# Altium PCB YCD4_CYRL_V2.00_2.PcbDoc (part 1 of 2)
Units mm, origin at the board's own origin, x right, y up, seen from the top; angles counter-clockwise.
Board outline 53 x 53 mm, 6 copper layers (Top Layer, Mid-Layer 1, Mid-Layer 3, Mid-Layer 4, Mid-Layer 5, Bottom Layer), stack 0.996 mm thick; 207 components, 114 nets, 645 pads, 437 vias.
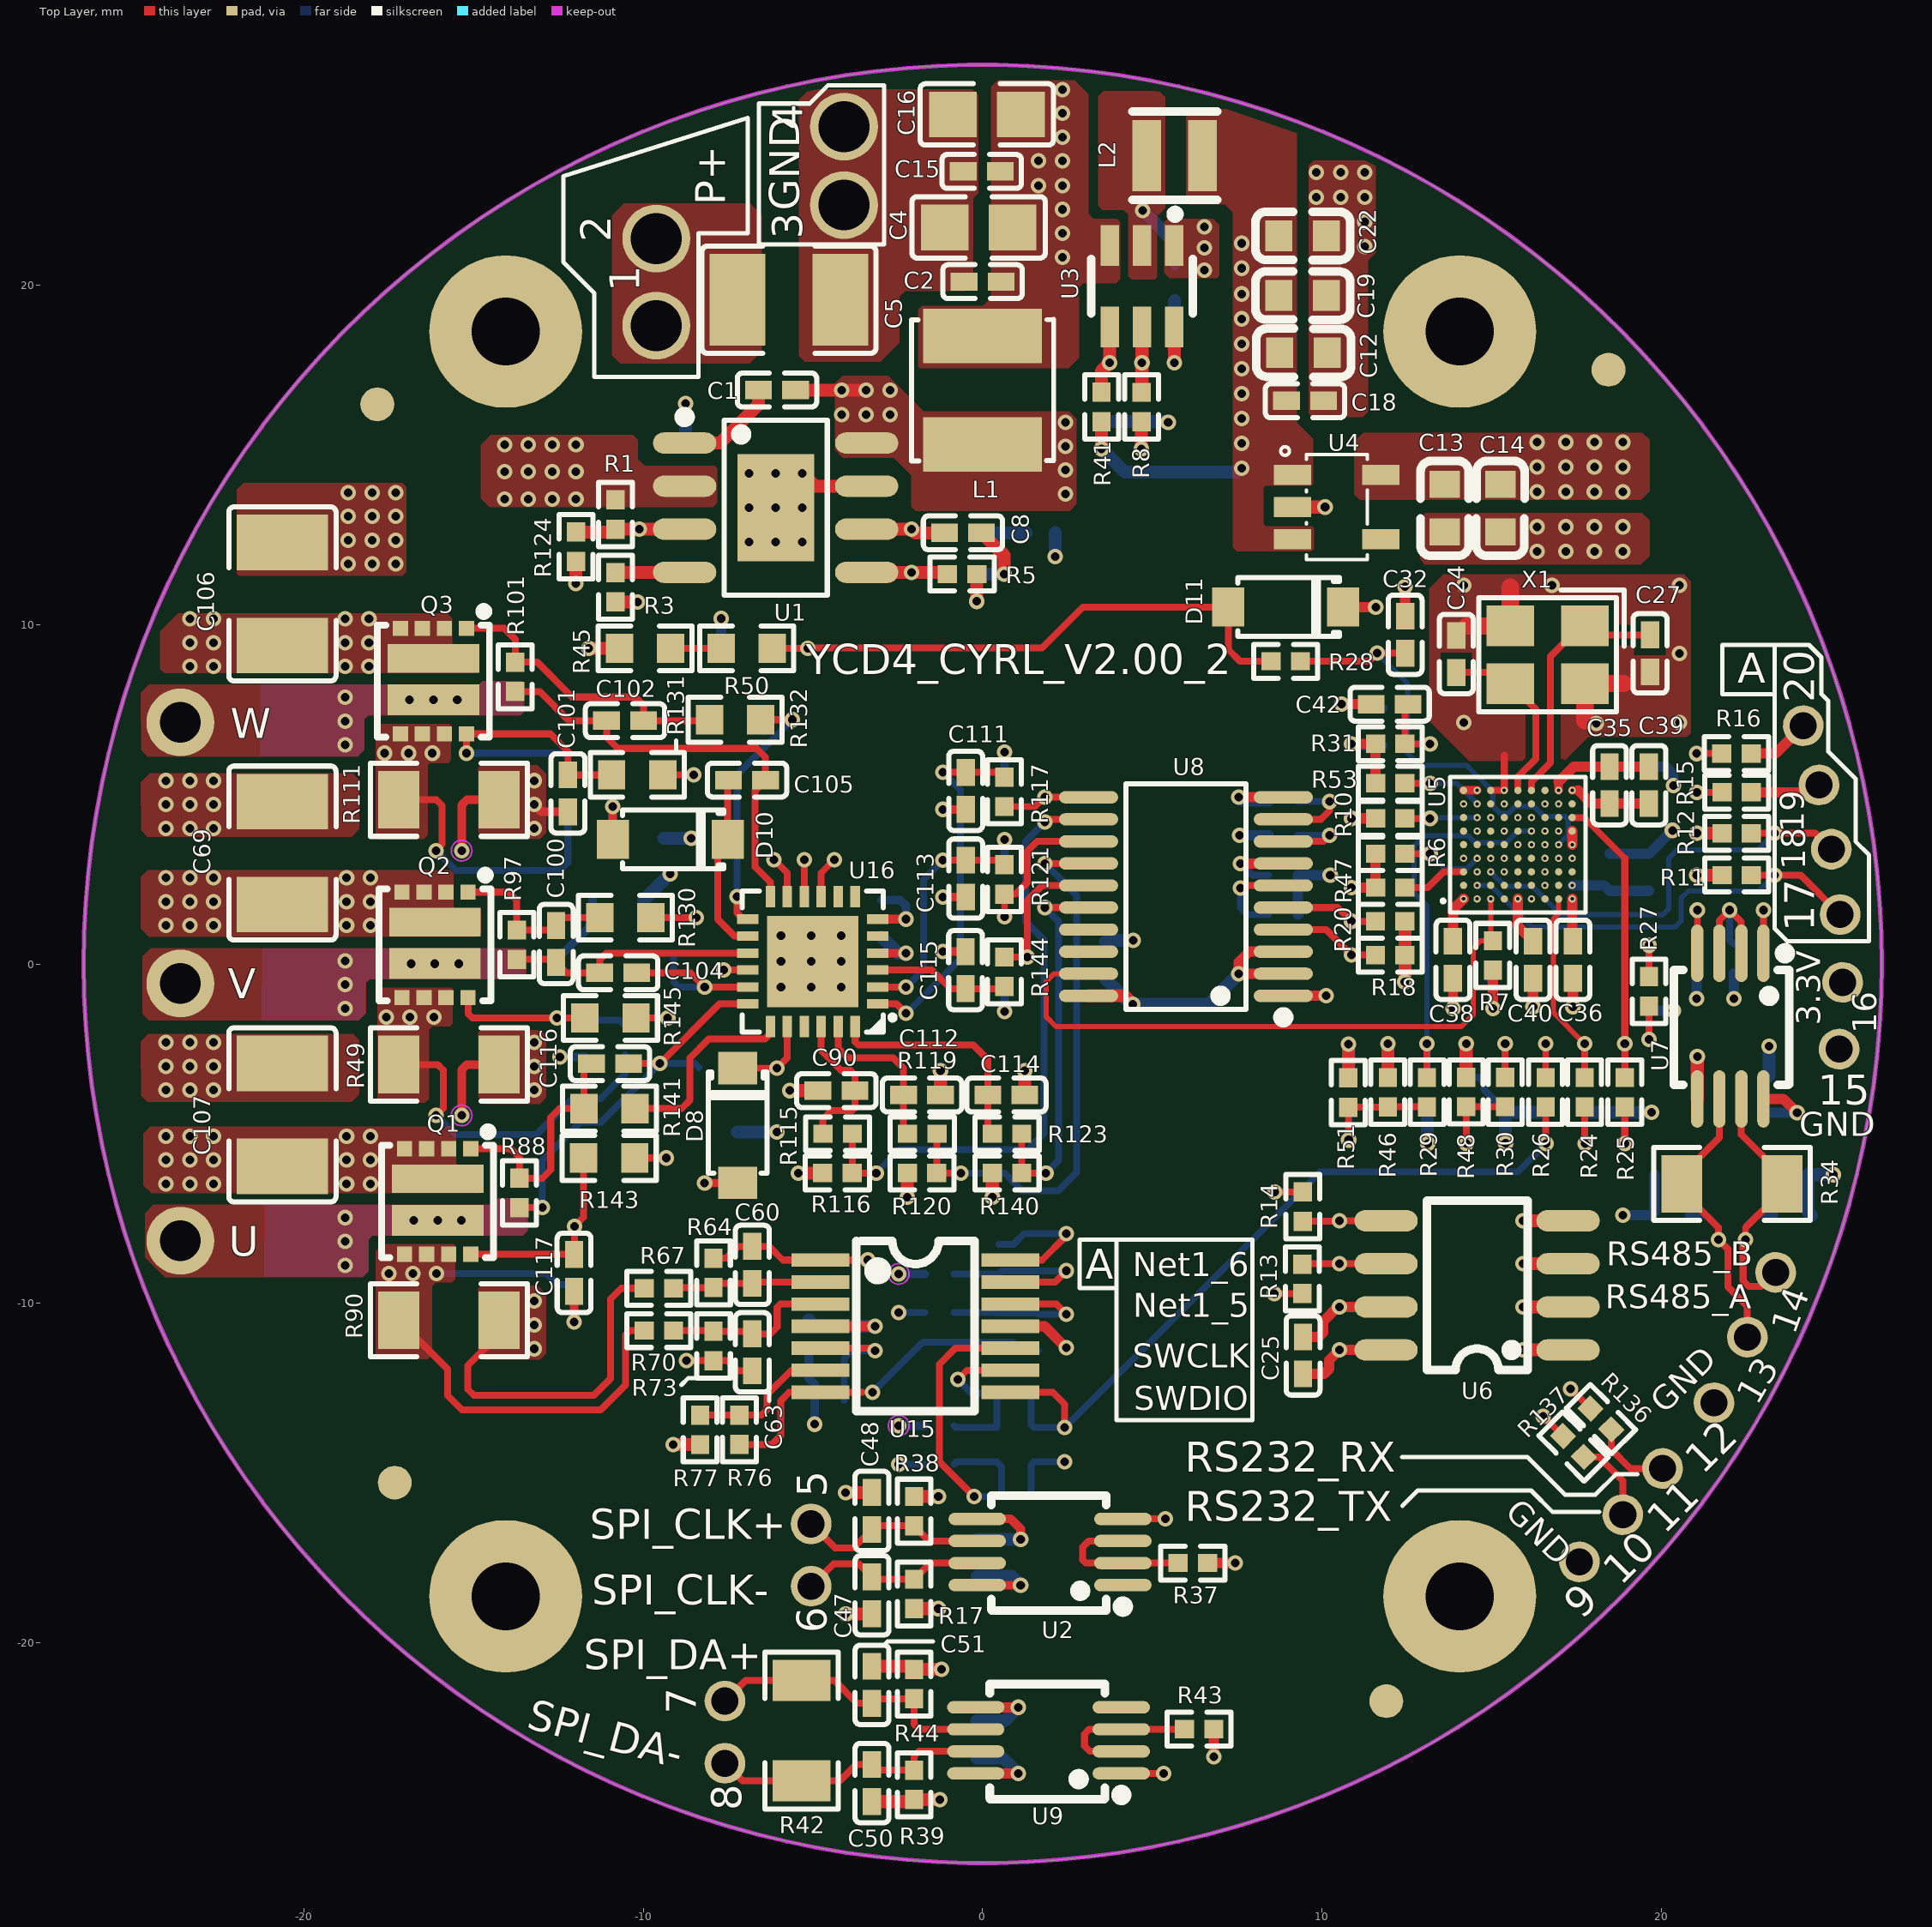
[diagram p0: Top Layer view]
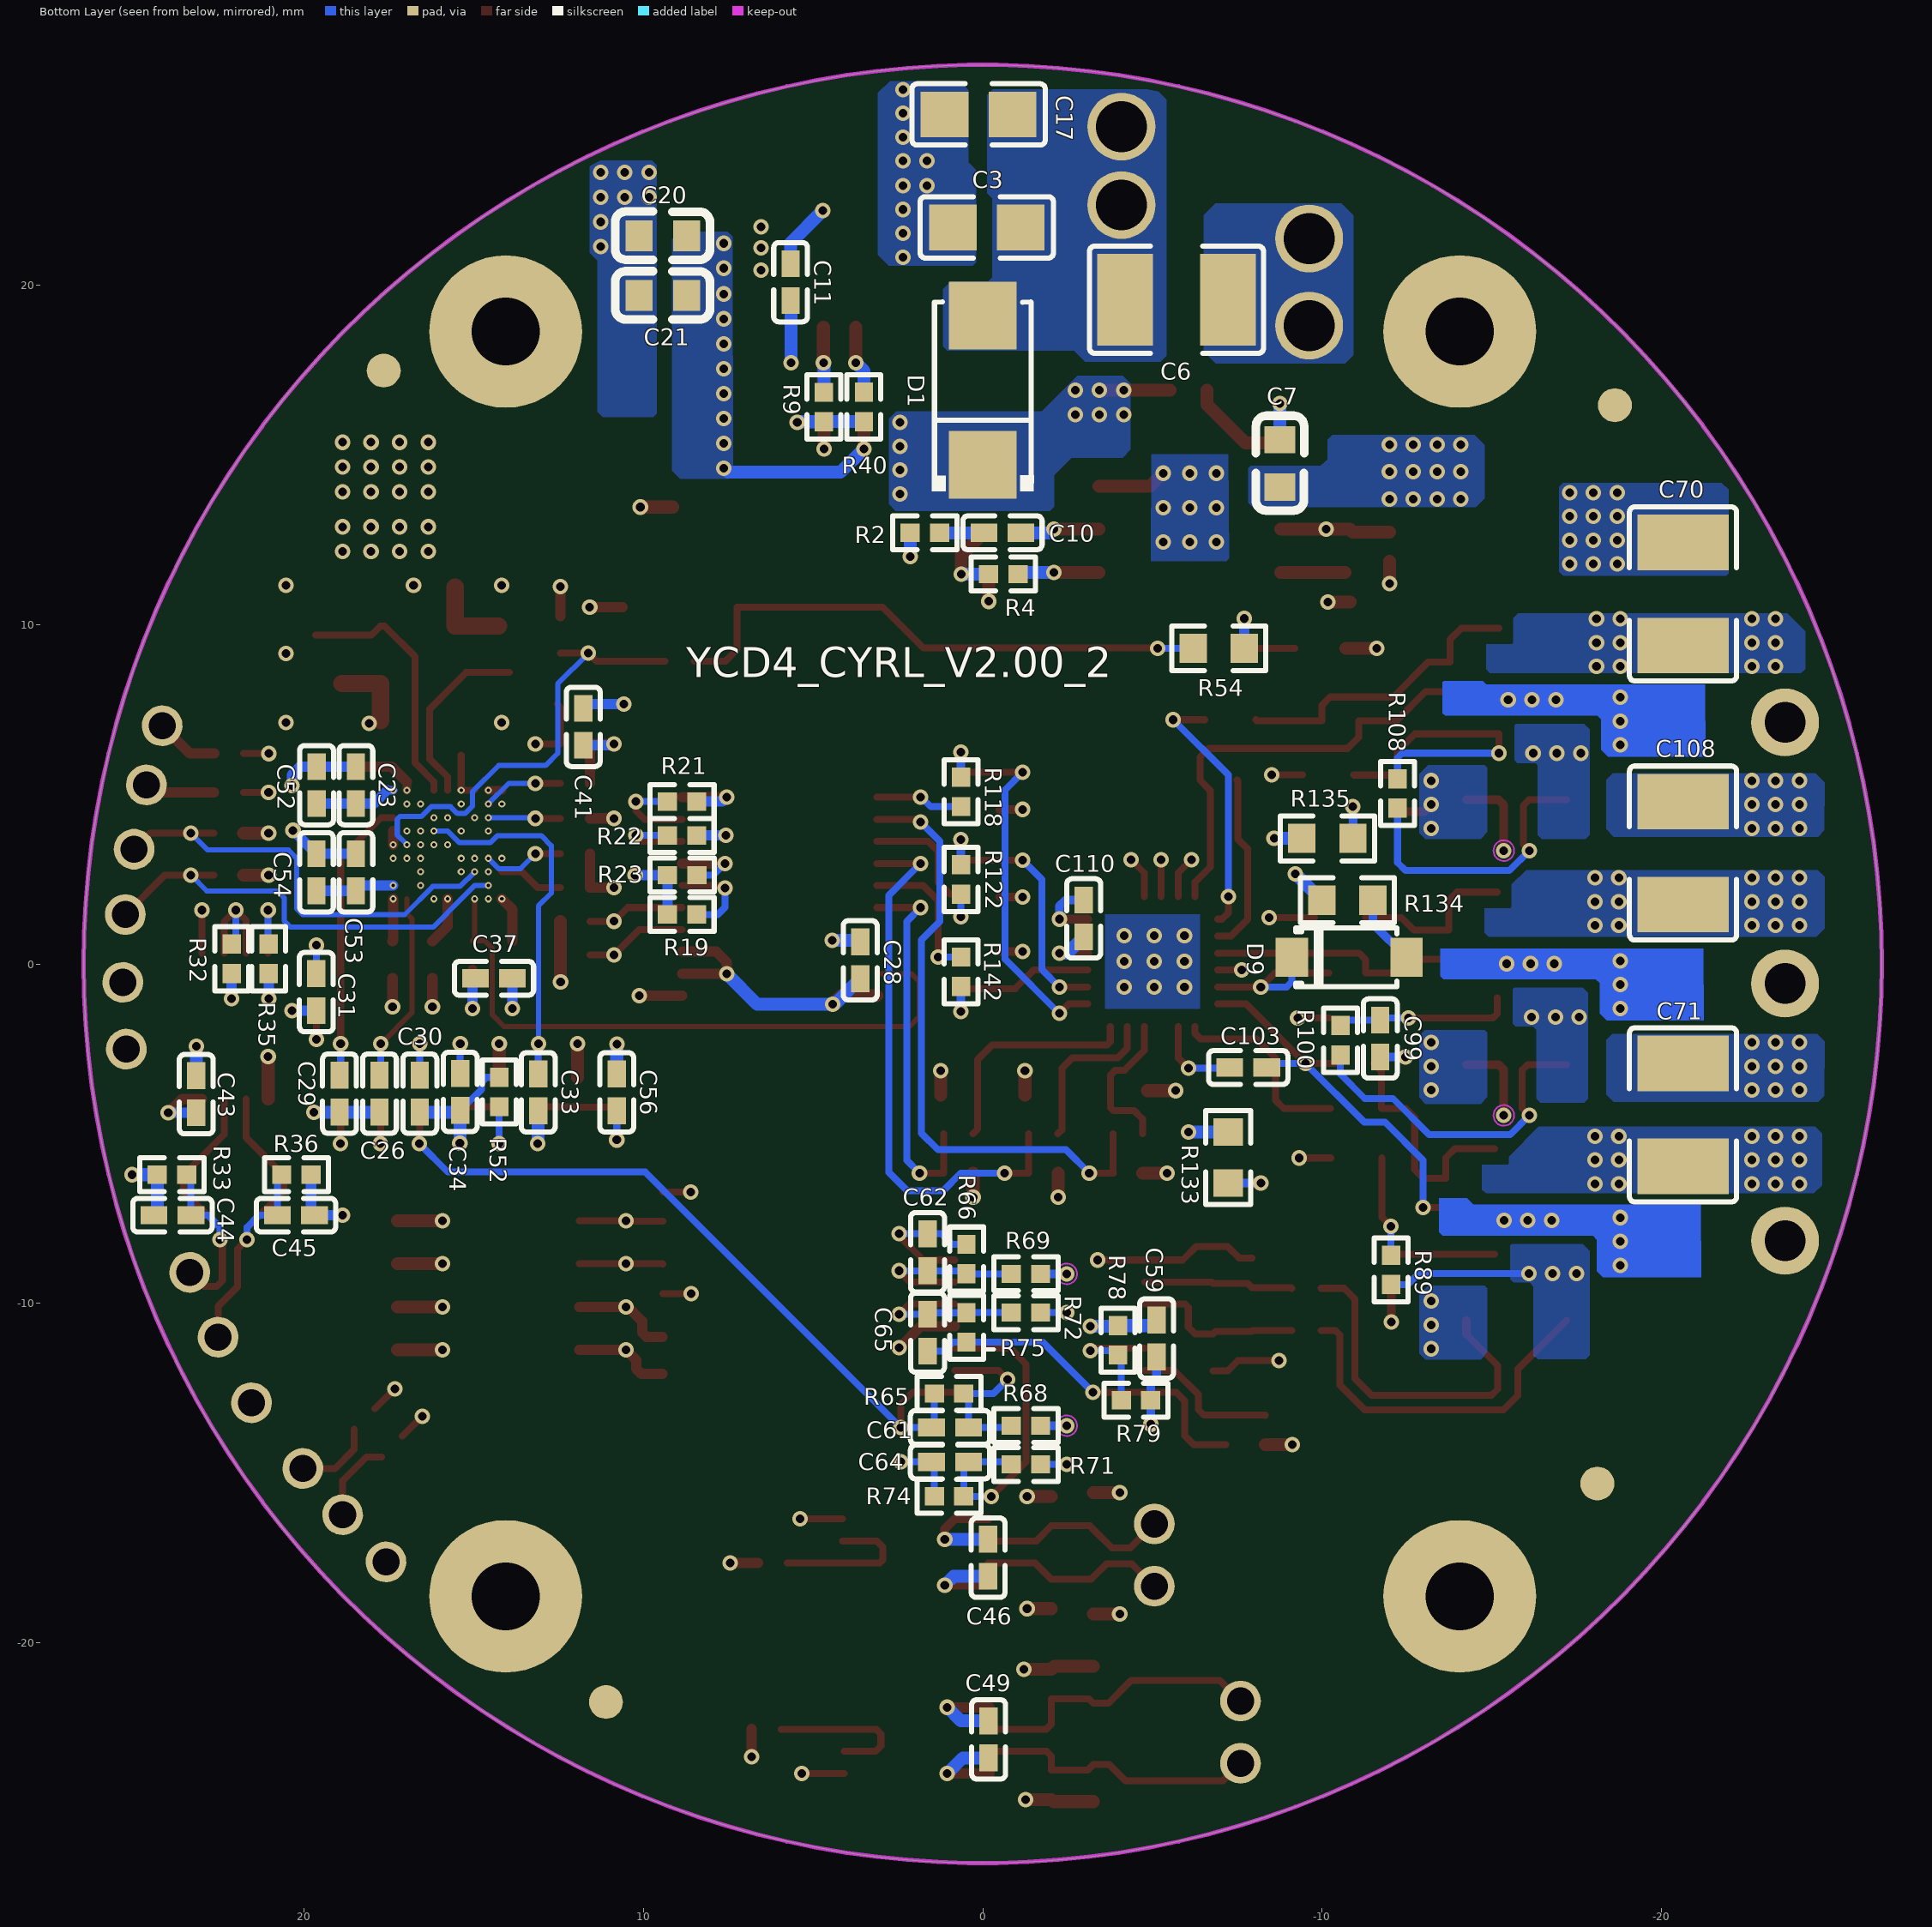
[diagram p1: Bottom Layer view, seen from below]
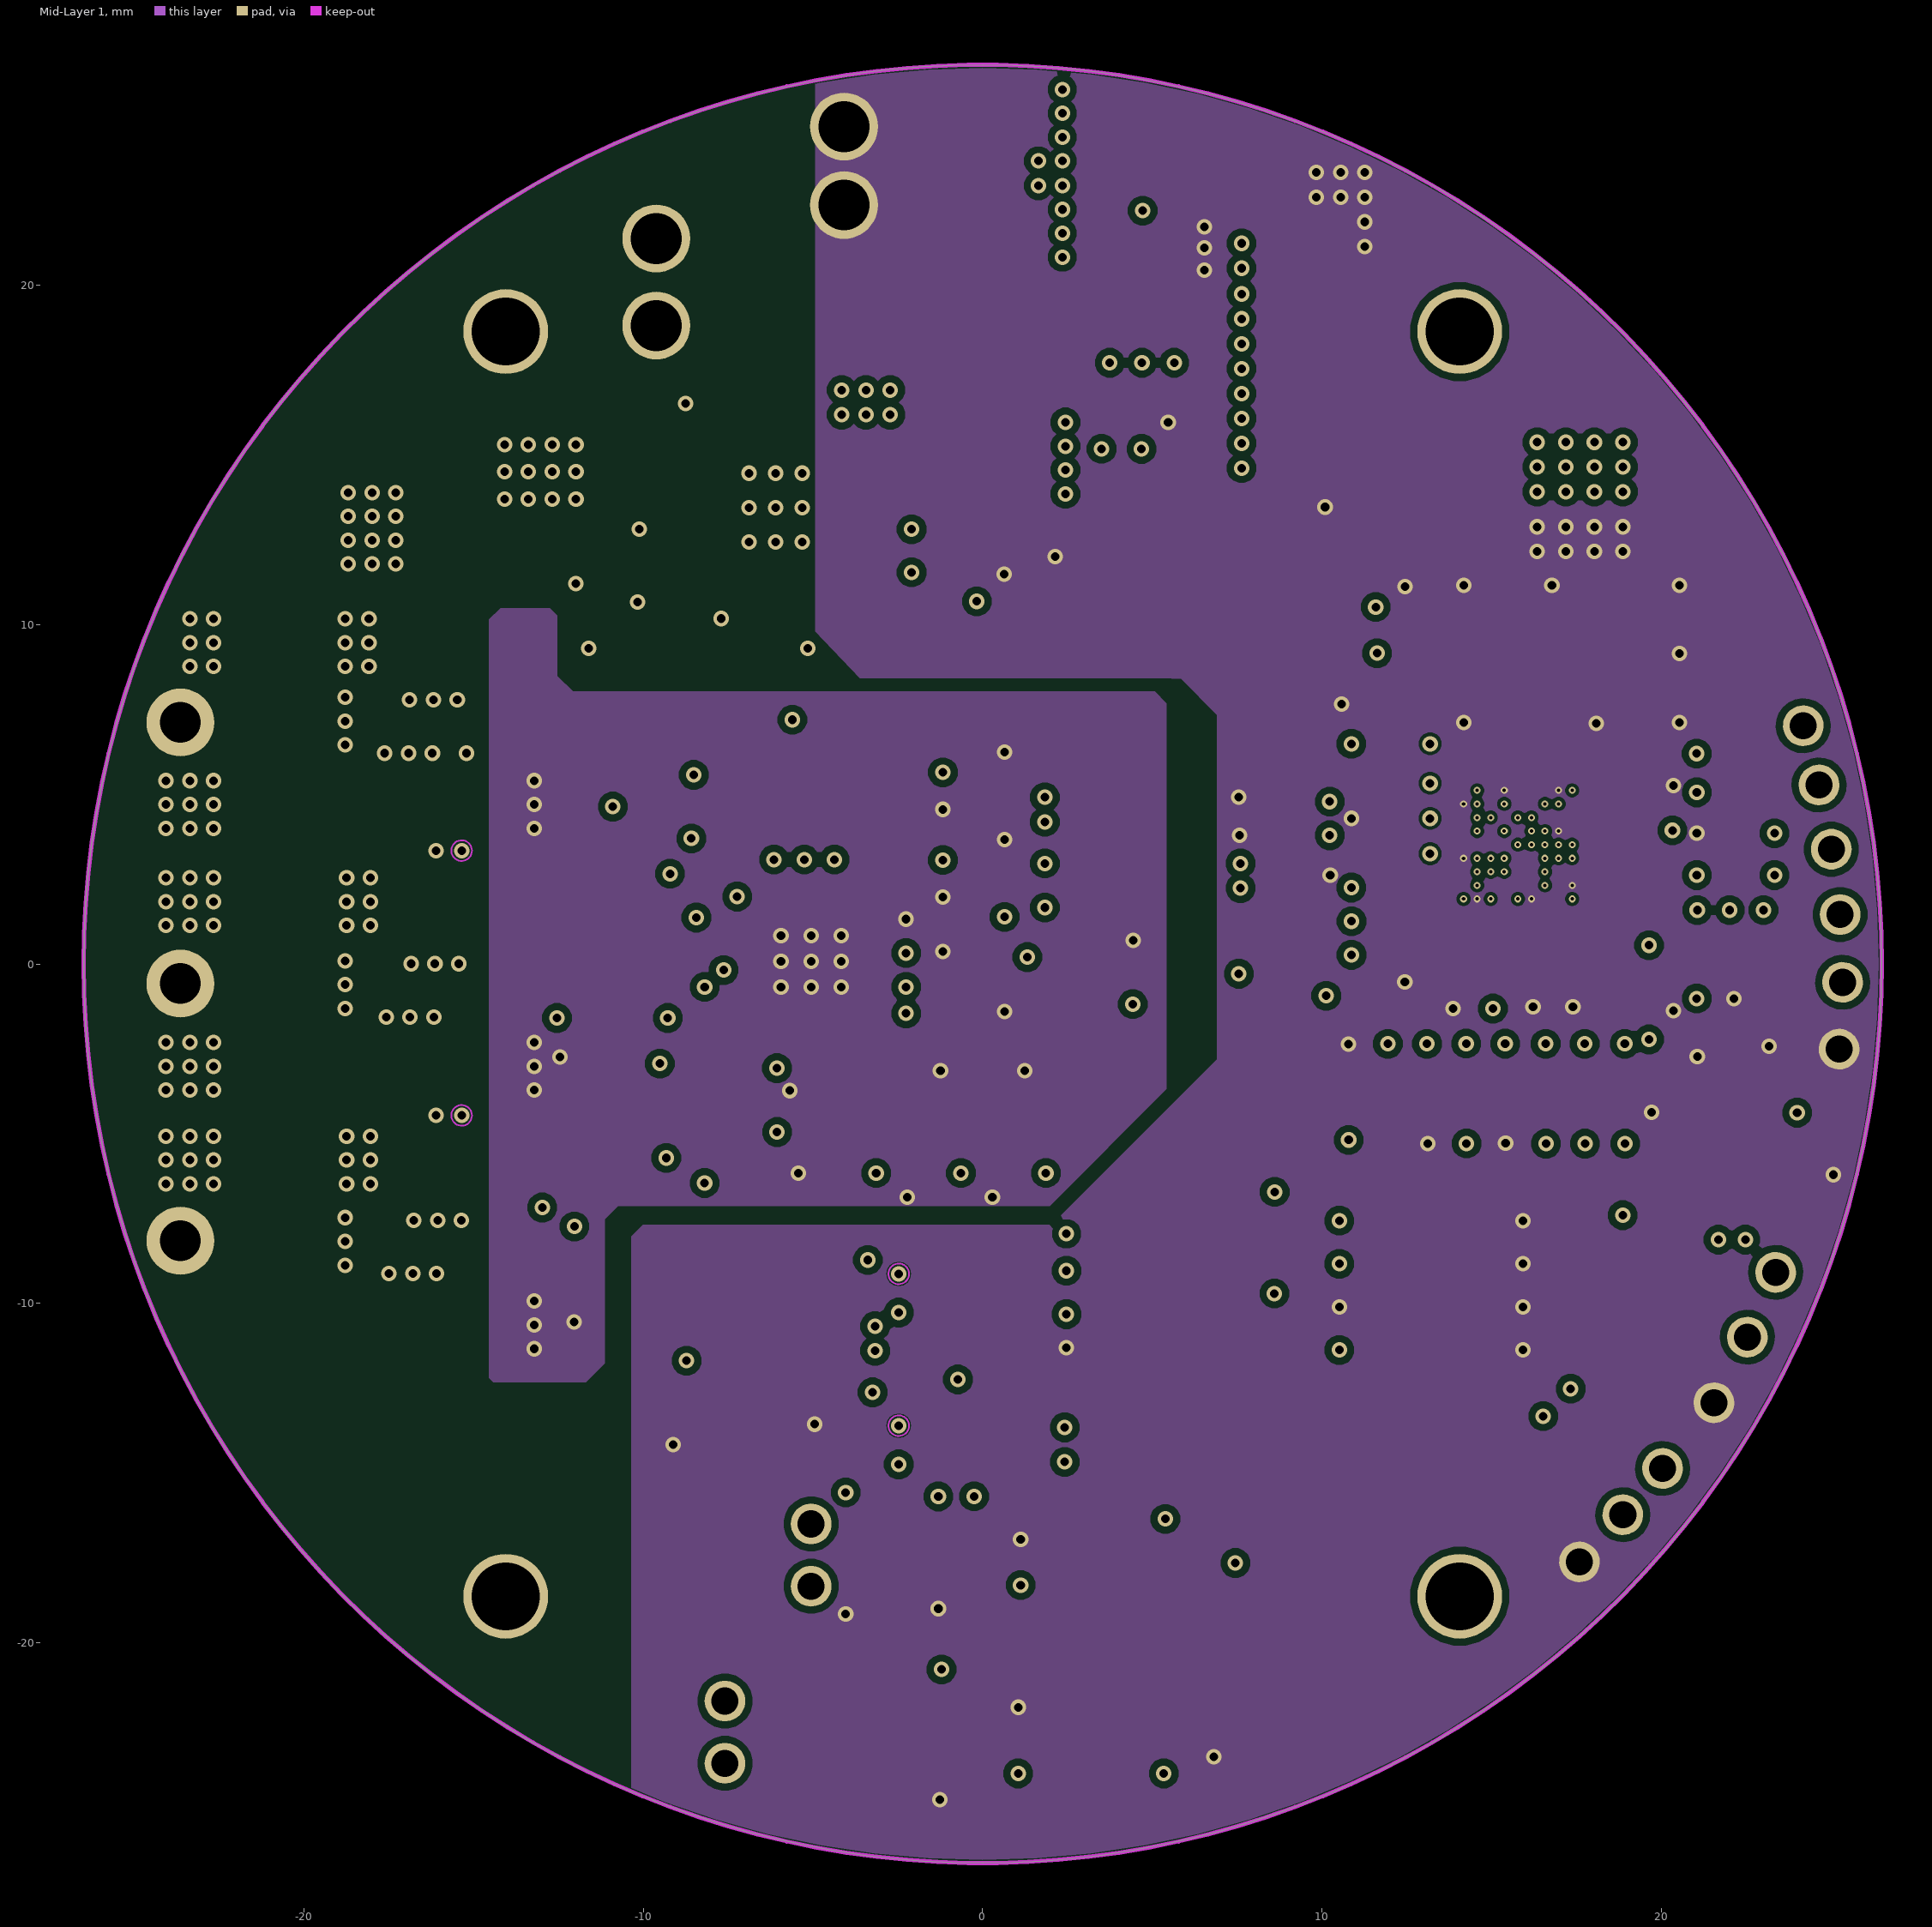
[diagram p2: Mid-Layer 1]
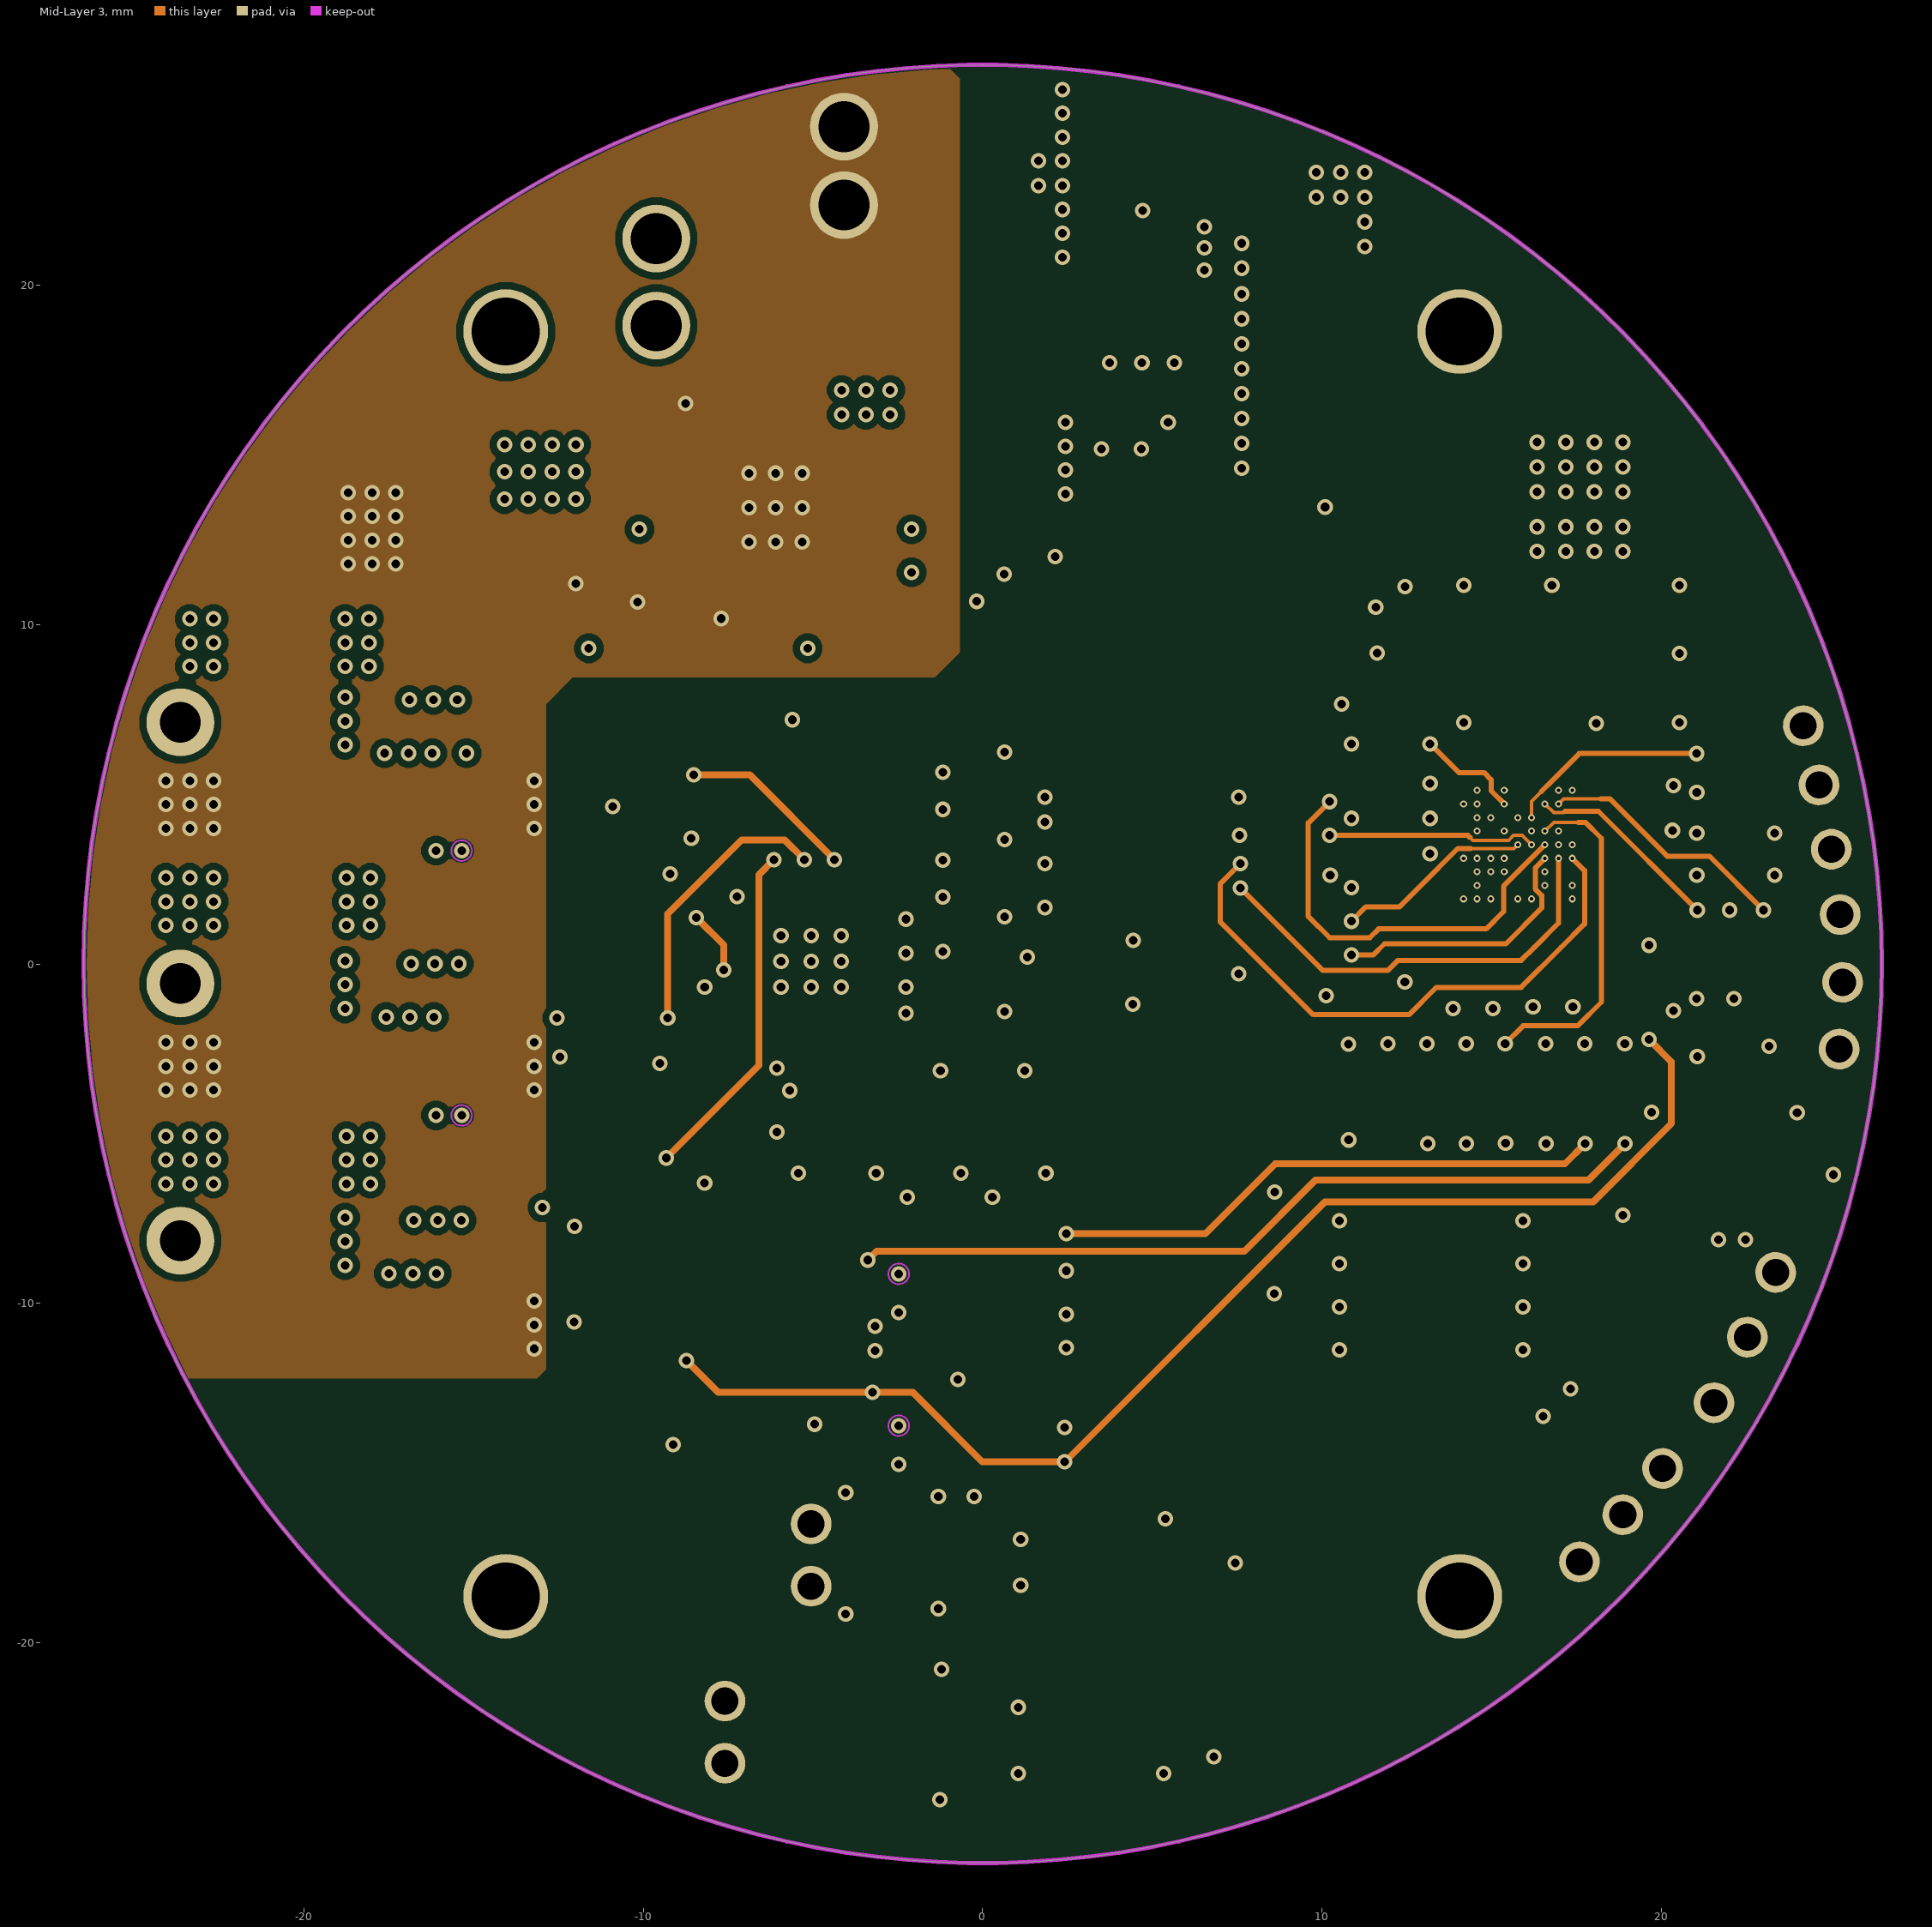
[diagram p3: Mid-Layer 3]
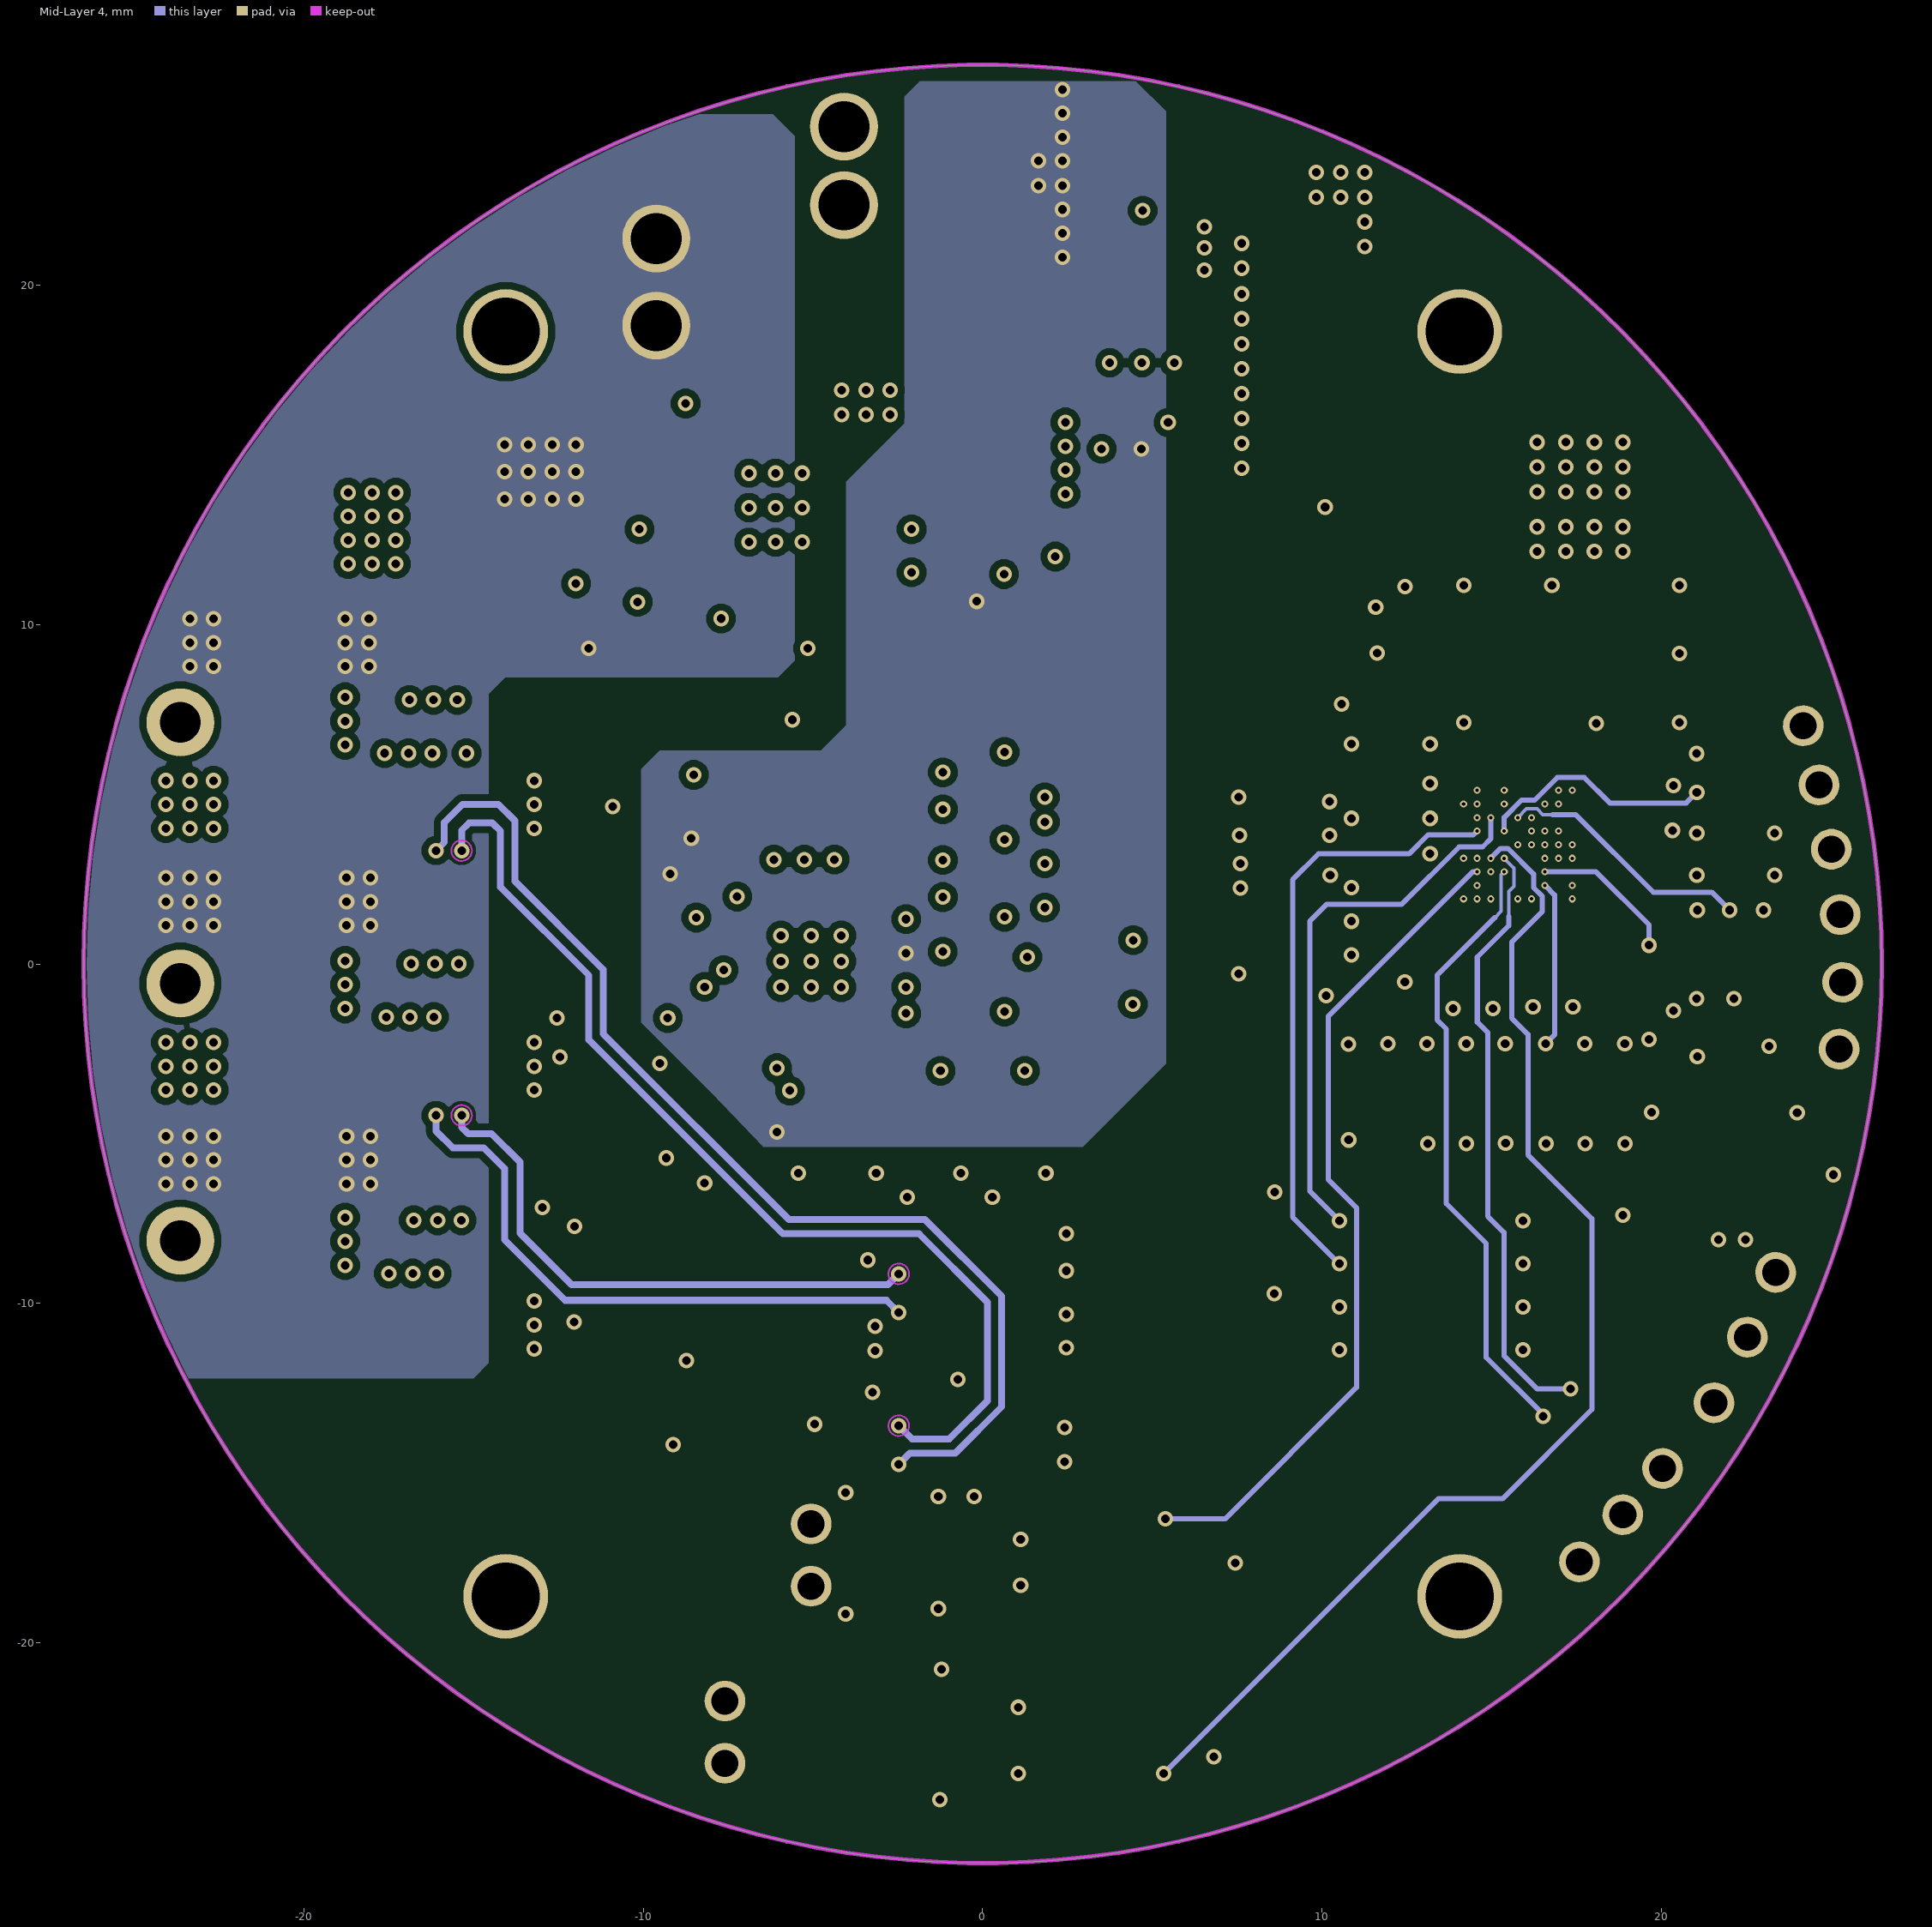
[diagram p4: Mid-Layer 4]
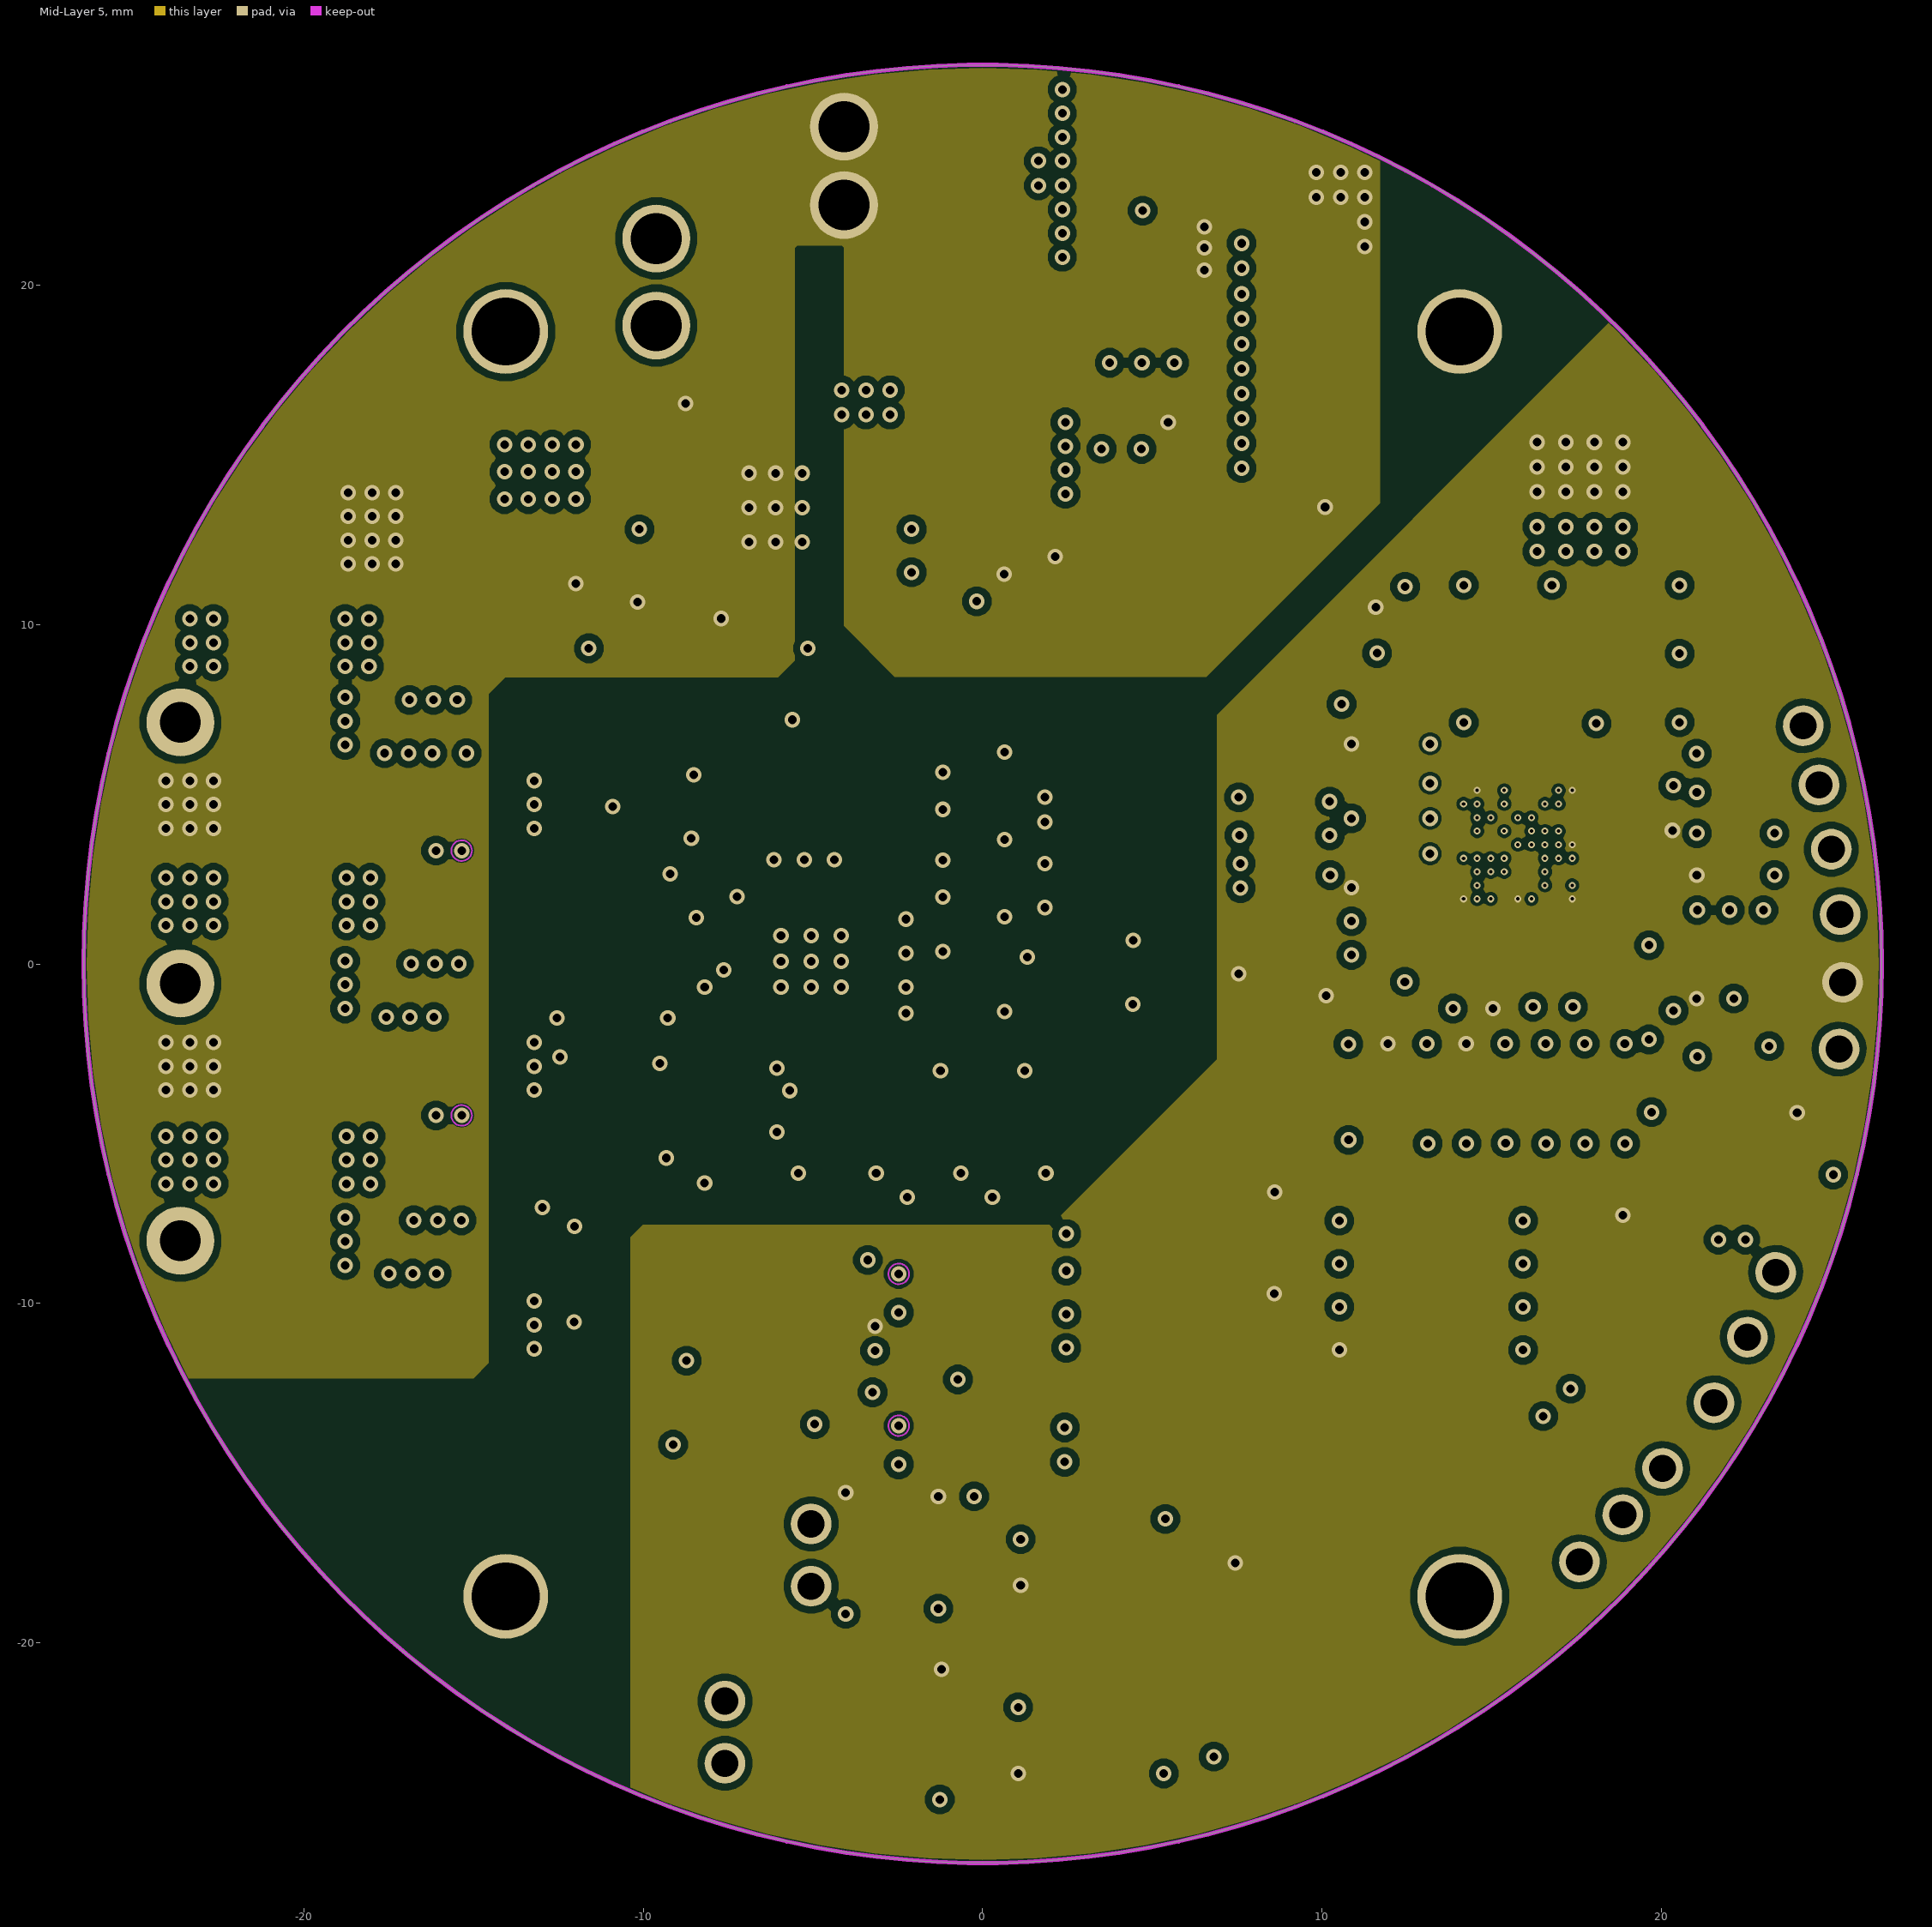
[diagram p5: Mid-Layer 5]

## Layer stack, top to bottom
Top Solder: solder mask 0.0102, Solder Resist, Dk 3.5
Top Layer: signal copper 0.0254
Dielectric 1: dielectric 0.127, FR-4, Dk 4.8
Mid-Layer 1: signal copper 0.0254
Dielectric2: dielectric 0.0508, FR-4, Dk 4.8
Mid-Layer 3: signal copper 0.0254
Dielectric5: dielectric 0.4877, FR-4, Dk 4.8
Mid-Layer 4: signal copper 0.0254
Dielectric3: dielectric 0.0508, FR-4, Dk 4.8
Mid-Layer 5: signal copper 0.0254
Dielectric4: dielectric 0.127, FR-4, Dk 4.8
Bottom Layer: signal copper 0.0254
Bottom Solder: solder mask 0.0102, Solder Resist, Dk 3.5

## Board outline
-26.5,0 ccw(c0,0) 0,-26.5 ccw(c0,0) 26.5,0 ccw(c0,0) 0,26.5 ccw(c0,0)

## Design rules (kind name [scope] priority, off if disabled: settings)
Clearance Clearance_keep [IsKeepOut] p1: gap=0.025 ignorepadtopadclearanceinfootprint=TRUE
Clearance Clearance_1 [WithinRoom('RoomDefinition') And (OnMid Or OnMultiLayer)] p2: gap=0.102 ignorepadtopadclearanceinfootprint=TRUE except(0: Arc-Hole Track-Hole SMDPad-Hole THPad-Hole Via-Hole Fill-Hole Poly-Hole Region-Hole Text-Hole; 0.152: Via-Via)
Clearance [WithinRoom('RoomDefinition') And (OnBottomLayer Or OnTopLayer)] p3: gap=0.127 ignorepadtopadclearanceinfootprint=TRUE except(0: Arc-Hole Track-Hole SMDPad-Hole THPad-Hole Via-Hole Fill-Hole Poly-Hole Region-Hole Text-Hole; 0.152: Via-Via)
Clearance copperThickness1oz [All] p4: gap=0.203 ignorepadtopadclearanceinfootprint=TRUE except(0: Arc-Hole Track-Hole SMDPad-Hole THPad-Hole Via-Hole Fill-Hole Poly-Hole Region-Hole Text-Hole; 0.152: Arc-Arc Arc-Track Arc-Via Track-Track Track-Via; 0.254: Via-Via)
ComponentClearance [All] p1: gap=0 collisioncheckmode=3 verticalgap=0 showdistances=FALSE
DiffPairsRouting differentialPair [All] p1: maxlimit=0.152 minlimit=0 mostfreqgap=0.152 toplayer_minwidth=0.127 toplayer_maxwidth=2.54 toplayer_prefwidth=0.254 midlayer1_minwidth=0.127 midlayer1_maxwidth=2.54 midlayer1_prefwidth=0.254 midlayer3_minwidth=0.127 midlayer3_maxwidth=2.54 midlayer3_prefwidth=0.254 midlayer4_minwidth=0.127 midlayer4_maxwidth=2.54 midlayer4_prefwidth=0.254 midlayer5_minwidth=0.127 midlayer5_maxwidth=2.54 midlayer5_prefwidth=0.254 bottomlayer_minwidth=0.127 bottomlayer_maxwidth=2.54 bottomlayer_prefwidth=0.254 maxuncoupledlength=0.254
FanoutControl Fanout_BGA [HasFootprint('WLCSP-90_L4.2-W4.0-C10-R9-P0.40-TL')] p1: bgadir=In bgaviamode=Closest fanoutstyle=BGA fanoutdirection=Alternating viagrid=0.025 // Fanout_BGA (Default Rule)
HoleSize [All] p1: absolutevalues=TRUE maxlimit=100 minlimit=0.025 maxpercent=80.000 minpercent=20.000
MinimumSolderMaskSliver [All] p1: minsoldermaskwidth=0
PasteMaskExpansion pasteMaskExpansion [All] p1: expansion=0
PlaneConnect innerPlane [All] p1: planeconnectstyle=Relief reliefexpansion=0.508 reliefentries=4 reliefconductorwidth=0.254 reliefairgap=0.254
PolygonConnect PolygonConnect_via [IsVia] p1: connectstyle=Direct reliefconductorwidth=0.254 reliefentries=4 polygonreliefangle="45 Angle" airgapwidth=0.254
PolygonConnect copperRegion [All] p2: connectstyle=Direct reliefconductorwidth=0.254 reliefentries=4 polygonreliefangle="90 Angle" airgapwidth=0.254
RoomDefinition [False vs False] p1: confinementstyle=ConfineIn formatcopy=TRUE lockcomponents=FALSE outline 12.898,6.491 18.804,6.491 18.804,0.489 12.898,0.489
RoutingVias viaSize [All] p1: holewidth=0.102 width=0.203 viastyle="Through Hole" minholewidth=0.001 minwidth=0.01 maxholewidth=6.3 maxwidth=10
SilkToSilkClearance [All] p1: silktosilkclearance=0
SilkToSolderMaskClearance [IsPad] p1: minsilkscreentomaskgap=0 clearancetoexposedcopper=TRUE
SolderMaskExpansion SolderMaskExpansion_1 [IsVia] p1: expansion=0.102 istentingtop=TRUE
SolderMaskExpansion solderMaskExpansion [All] p2: expansion=0.051 istentingtop=FALSE useseparateexpansions=TRUE expansionbottom=0.051 istentingbottom=FALSE
Width copperThickness1oz_1 [All] p1: maxlimit=2.54 minlimit=0.025 preferedwidth=0.025
17 further rules are at their usual default settings.

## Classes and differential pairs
component class 5_DRIVE: C69 C70 C71 C90 C99 C100 C101 C102 C103 C104 C105 C106 C107 C108 C110 C111 C112 C113 C114 C115 C116 C117 D8 D9 Q1 Q2 Q3 R49 R88 R89 R90 R97 R100 R101 R108 R111 R115 R116 R117 R118 R119 R120 R121 R122 R123 R130 R132 R133 R134 R140 R141 R142 R143 R144 R145 U16
component class 4_SAMP: C56 C59 C60 C61 C62 C63 C64 C65 D11 R45 R46 R48 R50 R51 R52 R54 R64 R65 R66 R67 R68 R69 R70 R71 R72 R73 R74 R75 R76 R77 R78 R79 U15
component class 3_COM: C43 C44 C45 C46 C47 C48 C49 C50 C51 R17 R32 R33 R34 R35 R36 R37 R38 R39 R42 R43 R44 R136 R137 U2 U7 U9
component class 2_ARM: C23 C24 C25 C26 C27 C28 C29 C30 C31 C32 C33 C34 C35 C36 C37 C38 C39 C40 C41 C42 C52 C53 C54 CN1 R6 R7 R10 R11 R12 R13 R14 R15 R16 R18 R19 R20 R21 R22 R23 R24 R25 R26 R27 R28 R29 R30 R31 R47 R53 U5 U6 U8 X1
component class 1_POWER: C1 C2 C3 C4 C5 C6 C7 C8 C10 C11 C12 C13 C14 C15 C16 C17 C18 C19 C20 C21 C22 D1 L1 L2 R1 R2 R3 R4 R5 R8 R9 R40 R41 R124 U1 U3 U4

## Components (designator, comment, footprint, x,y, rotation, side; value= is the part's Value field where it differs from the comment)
C1 "100nF" C0402 -6.064,16.914 r180 top
C2 "100nF" C0402 -0.004,20.108 r180 top
C3 "10uF" C0805 -0.119,21.709 r180 bottom
C4 "10uF" C0805 -0.119,21.709 r180 top
C5 "10uF" C1210 -5.712,19.576 r0 top
C6 "10uF" C1210 -5.712,19.576 r0 bottom
C7 "100nF" C0603 -8.758,14.752 r270 bottom
C8 "220pF" C0402 -0.582,12.706 r0 top
C10 "1nF" C0402 -0.582,12.706 r0 bottom
C11 "100nF" C0402 5.662,20.093 r90 bottom
C12 "10uF" C0603 9.452,18.015 r180 top
C13 "10uF" C0603 13.615,13.432 r90 top
C14 "10uF" C0603 15.262,13.432 r90 top
C15 "100nF" C0402 -0.029,23.357 r180 top
C16 "10uF" C0805 0.121,25.036 r180 top
C17 "10uF" C0805 0.121,25.036 r180 bottom
C18 "100nF" C0402 9.5,16.597 r0 top
C19 "10uF" C0603 9.43,19.701 r180 top
C20 "10uF" C0603 9.43,21.46 r180 bottom
C21 "10uF" C0603 9.43,19.701 r180 bottom
C22 "10uF" C0603 9.43,21.46 r180 top
C23 "10nF" C0402 18.476,5.269 r270 bottom value=100nF
C24 "20pF" C0402 13.958,9.133 r90 top
C25 "100nF" C0402 9.442,-11.538 r270 top
C26 "100pF" C0402 17.781,-3.823 r90 bottom
C27 "20pF" C0402 19.668,9.152 r270 top
C28 "100nF" C0402 3.611,0.107 r270 bottom
C29 "100pF" C0402 18.958,-3.823 r90 bottom
C30 "100pF" C0402 16.592,-3.823 r90 bottom
C31 "100nF" C0402 19.641,-0.83 r270 bottom
C32 "100nF" C0402 12.45,9.704 r90 top
C33 "100nF" C0402 13.102,-3.785 r270 bottom
C34 "100nF" C0402 15.401,-3.772 r270 bottom
C35 "100nF" C0402 18.476,5.269 r90 top
C36 "100nF" C0402 17.396,0.123 r270 top
C37 "100nF" C0402 14.406,-0.422 r180 bottom
C38 "100nF" C0402 13.861,0.123 r270 top
C39 "100nF" C0402 19.635,5.269 r90 top
C40 "100nF" C0402 16.22,0.123 r270 top
C41 "100nF" C0402 11.774,6.988 r90 bottom
C42 "100nF" C0402 11.993,7.656 r0 top
C43 "100nF" C0402 23.181,-3.84 r270 bottom
C44 "100pF" C0402 23.882,-7.406 r0 bottom
C45 "100pF" C0402 20.243,-7.406 r0 bottom
C46 "100nF" C0402 -0.159,-17.5 r270 bottom
C47 "100pF" C0402 -3.263,-18.61 r270 top
C48 "100pF" C0402 -3.263,-16.122 r270 top
C49 "100nF" C0402 -0.174,-22.855 r270 bottom
C50 "100pF" C0402 -3.263,-24.142 r270 top
C51 "100pF" C0402 -3.263,-21.248 r270 top
C52 "2.2uF" C0402 19.635,5.269 r90 bottom
C53 "10nF" C0402 18.476,2.7 r90 bottom value=100nF
C54 "2.2uF" C0402 19.638,2.7 r270 bottom
C56 "100nF" C0402 10.787,-3.786 r90 bottom
C59 "100nF" C0402 -5.125,-11.039 r90 bottom
C60 "20pF" C0402 -6.79,-8.87 r90 top
C61 "20pF" C0402 0.962,-13.661 r0 bottom
C62 "20pF" C0402 1.627,-8.498 r90 bottom
C63 "20pF" C0402 -6.79,-11.448 r90 top
C64 "20pF" C0402 0.962,-14.677 r180 bottom
C65 "20pF" C0402 1.627,-10.868 r90 bottom
C69 "10uF" C1210 -20.642,3.268 r90 top
C70 "10uF" C1210 -20.642,10.905 r90 bottom
C71 "10uF" C1210 -20.642,-4.448 r90 bottom
C90 "100pF" C0402 -4.313,-3.734 r0 top
C99 "1nF" C0402 -11.716,-2.198 r90 bottom
C100 "1nF" C0402 -12.573,0.588 r90 top
C101 "1nF" C0402 -12.225,5.027 r90 top
C102 "1nF" C0402 -10.542,7.169 r0 top
C103 "220nF" C0402 -7.824,-3.054 r0 bottom
C104 "220nF" C0402 -10.744,-0.263 r0 top
C105 "220nF" C0402 -6.947,5.419 r180 top
C106 "10uF" C1210 -20.642,10.905 r90 top
C107 "10uF" C1210 -20.642,-4.448 r90 top
C108 "10uF" C1210 -20.642,3.268 r90 bottom
C110 "220nF" C0402 -2.978,1.341 r270 bottom
C111 "100pF" C0402 -0.503,5.1 r90 top
C112 "100pF" C0402 -1.789,-3.862 r180 top
C113 "100pF" C0402 -0.503,2.516 r90 top
C114 "100pF" C0402 0.696,-3.862 r180 top
C115 "100pF" C0402 -0.506,-0.183 r270 top
C116 "1nF" C0402 -10.985,-2.937 r180 top
C117 "1nF" C0402 -12.045,-9.107 r90 top
D1 "US1D" SMA_L4.3-W2.6-LS5.1-RD -0.004,16.908 r90 bottom
D8 "DSF1D E1D" SOD-123_L2.8-W1.8-LS3.7-RD -7.226,-4.764 r270 top
D9 "DSF1D E1D" SOD-123_L2.8-W1.8-LS3.7-RD -10.804,0.191 r180 bottom
D10 "DSF1D E1D" SOD-123_L2.8-W1.8-LS3.7-RD -9.21,3.675 r180 top
D11 "DSF1D E1D" SOD-123_L2.8-W1.8-LS3.7-RD 8.928,10.519 r180 top
L1 "10uH" IND-SMD_L4.0-W4.0 -0.004,16.908 r90 top
L2 "4.7uH" IND-SMD_L2.5-W2.1 5.656,23.825 r0 top
Q1 "SiZ254DT-T1-GE3" POWERPAIR-8_L3.3-W3.3-P0.65-BL_SIZ260DT-T1-GE3 -16.066,-7.001 r180 top
Q2 "SiZ254DT-T1-GE3" POWERPAIR-8_L3.3-W3.3-P0.65-BL_SIZ260DT-T1-GE3 -16.145,0.562 r180 top
Q3 "SiZ254DT-T1-GE3" POWERPAIR-8_L3.3-W3.3-P0.65-BL_SIZ260DT-T1-GE3 -16.19,8.335 r180 top
R1 "47kΩ" R0402 -10.825,13.245 r90 top value=200kΩ
R2 "47kΩ" R0402 1.708,12.707 r0 bottom
R3 "200kΩ" R0402 -10.825,11.103 r90 top
R4 "10kΩ" R0402 -0.608,11.489 r0 bottom
R5 "120kΩ" R0402 -0.608,11.489 r0 top
R6 "10kΩ" R0402 12.011,3.248 r180 top
R7 "10kΩ" R0402 15.037,0.25 r270 top
R8 "15kΩ" R0402 4.68,16.414 r270 top value=200kΩ
R9 "2kΩ" R0402 4.68,16.414 r270 bottom value=30kΩ
R10 "10kΩ" R0402 12.011,4.29 r180 top
R11 "10kΩ" R0402 22.223,2.618 r0 top
R12 "10kΩ" R0402 22.223,3.851 r0 top
R13 "5.1kΩ" R0402 9.423,-9.281 r270 top
R14 "5.1kΩ" R0402 9.43,-7.152 r270 top
R15 "2kΩ" R0402 22.223,5.057 r0 top
R16 "2kΩ" R0402 22.219,6.2 r0 top
R17 "5.1kΩ" R0402 -2.022,-18.568 r270 top
R18 "10kΩ" R0402 12.01,0.261 r0 top
R19 "10kΩ" R0402 8.862,1.457 r0 bottom
R20 "10kΩ" R0402 12.01,1.253 r0 top
R21 "10kΩ" R0402 8.862,4.784 r180 bottom
R22 "10kΩ" R0402 8.862,3.789 r180 bottom
R23 "10kΩ" R0402 8.86,2.618 r0 bottom
R24 "100Ω" R0402 17.742,-3.78 r90 top value=2kΩ
R25 "100Ω" R0402 18.925,-3.78 r90 top value=2kΩ
R26 "100Ω" R0402 16.592,-3.78 r90 top value=2kΩ
R27 "2kΩ" R0402 19.639,-0.808 r90 top
R28 "2kΩ" R0402 8.932,8.921 r0 top
R29 "2kΩ" R0402 13.094,-3.781 r90 top
R30 "2kΩ" R0402 15.399,-3.777 r90 top
R31 "10kΩ" R0402 12.011,6.487 r180 top
R32 "5.1kΩ" R0402 22.137,0.15 r270 bottom
R33 "5.1kΩ" R0402 23.898,-6.211 r0 bottom
R34 "120Ω" R1206 22.083,-6.482 r0 top
R35 "5.1kΩ" R0402 21.045,0.15 r90 bottom
R36 "5.1kΩ" R0402 20.23,-6.211 r0 bottom
R37 "5.1kΩ" R0402 6.193,-17.656 r0 top
R38 "5.1kΩ" R0402 -2.022,-16.128 r270 top
R39 "5.1kΩ" R0402 -2.022,-24.194 r270 top
R40 "10kΩ" R0402 3.502,16.417 r270 bottom
R41 "52.3kΩ" R0402 3.502,16.417 r270 top
R42 "120Ω" R1206 -5.337,-22.597 r270 top
R43 "5.1kΩ" R0402 6.378,-22.553 r0 top
R44 "5.1kΩ" R0402 -2.022,-21.225 r270 top
R45 "18kΩ" R0603 -9.953,9.302 r180 top
R46 "5.1kΩ" R0402 11.942,-3.781 r90 top
R47 "10kΩ" R0402 12.011,2.25 r180 top
R48 "10kΩ" R0402 14.25,-3.775 r270 top
R49 "50mΩ" 1206R -15.736,-2.966 r180 top
R50 "18kΩ" R0603 -6.96,9.302 r180 top
R51 "NTCG103JF103FT1" R0402 10.776,-3.792 r270 top
R52 "2kΩ" R0402 14.25,-3.775 r270 bottom
R53 "10kΩ" R0402 12.011,5.324 r180 top
R54 "2kΩ" R0603 -6.96,9.302 r0 bottom
R64 "13kΩ" R0402 -7.936,-9.105 r90 top
R65 "13kΩ" R0402 0.992,-12.661 r0 bottom
R66 "13kΩ" R0402 0.479,-8.697 r90 bottom
R67 "1kΩ" R0402 -9.545,-9.56 r0 top
R68 "1kΩ" R0402 -1.274,-13.61 r0 bottom
R69 "1kΩ" R0402 -1.274,-9.136 r0 bottom
R70 "1kΩ" R0402 -9.545,-10.806 r0 top
R71 "1kΩ" R0402 -1.274,-14.749 r0 bottom
R72 "1kΩ" R0402 -1.274,-10.275 r0 bottom
R73 "13kΩ" R0402 -7.936,-11.261 r90 top
R74 "13kΩ" R0402 0.993,-15.693 r180 bottom
R75 "13kΩ" R0402 0.479,-10.713 r90 bottom
R76 "1kΩ" R0402 -7.171,-13.732 r270 top
R77 "2kΩ" R0402 -8.329,-13.734 r90 top
R78 "2kΩ" R0402 -3.989,-11.093 r270 bottom
R79 "1kΩ" R0402 -4.517,-12.861 r0 bottom
R88 "10kΩ" R0402 -13.653,-6.747 r90 top
R89 "10kΩ" R0402 -12.035,-9.016 r90 bottom
R90 "50mΩ" R1206 -15.736,-10.501 r180 top
R97 "10kΩ" R0402 -13.732,0.566 r90 top
R100 "10kΩ" R0402 -10.545,-2.249 r90 bottom
R101 "10kΩ" R0402 -13.777,8.462 r90 top
R108 "10kΩ" R0402 -12.227,5.025 r90 bottom
R111 "50mΩ" R1206 -15.736,4.838 r180 top
R115 "100Ω" R0402 -4.276,-5.005 r180 top
R116 "10kΩ" R0402 -4.285,-6.163 r0 top
R117 "100Ω" R0402 0.643,5.072 r90 top
R118 "10kΩ" R0402 0.643,5.072 r270 bottom
R119 "100Ω" R0402 -1.782,-5.005 r180 top
R120 "10kΩ" R0402 -1.788,-6.163 r0 top
R121 "100Ω" R0402 0.643,2.49 r90 top
R122 "10kΩ" R0402 0.643,2.49 r270 bottom
R123 "100Ω" R0402 0.718,-5.005 r180 top
R124 "5.1kΩ" R0402 -11.989,12.296 r90 top value=25kΩ
R130 "7.5Ω" R0603 -10.536,1.366 r180 top
R131 "7.5Ω" R0603 -10.184,5.572 r180 top
R132 "7.5Ω" R0603 -7.3,7.197 r180 top
R133 "7.5Ω" R0603 -7.234,-5.709 r90 bottom
R134 "7.5Ω" R0603 -10.75,1.878 r0 bottom
R135 "7.5Ω" R0603 -10.16,3.699 r0 bottom
R136 "100Ω" R0402 18.222,-13.413 r315 top value=2kΩ
R137 "100Ω" R0402 17.412,-14.222 r315 top value=2kΩ
R140 "10kΩ" R0402 0.718,-6.163 r0 top
R141 "7.5Ω" R0603 -10.999,-4.263 r180 top
R142 "10kΩ" R0402 0.643,-0.232 r90 bottom
R143 "7.5Ω" R0603 -11.008,-5.718 r180 top
R144 "100Ω" R0402 0.643,-0.232 r270 top
R145 "7.5Ω" R0603 -10.971,-1.594 r180 top
U1 "SCT2650STER" ESOP-8_L4.9-W3.9-P1.27-LS6.0-BL-EP-2 -6.103,13.447 r270 top
U2 "SIT3485EUA" MSOP-8_L3.0-W3.0-P0.65-LS5.0-BL 1.984,-17.332 r90 top
U3 "SCT2230CTVBR" TSOT-23-6_L2.9-W1.6-P0.95-LS2.8-BL 4.694,19.971 r180 top
U4 "XC6219B332MR" SOT-23-5_L3.0-W1.7-P0.95-LS2.8-BR 10.436,13.465 r180 top
U5 "GD32G553MEY7TR" GD32G553MEY7TR 17.773,1.515 r90 top
U6 "AT24C64M/TR" SOP-8_L4.9-W3.9-P1.27-LS6.0-BL 14.57,-9.472 r90 top
U7 "SIT3485EUA" MSOP-8_L3.0-W3.0-P0.65-LS5.0-BL 22.037,-1.833 r180 top
U8 "AIP74HC245TA.TR" TSSOP-20_L6.5-W4.4-P0.65-LS6.4-BL 5.991,1.986 r90 top
U9 "SIT3485EUA" MSOP-8_L3.0-W3.0-P0.65-LS5.0-BL 1.939,-22.884 r90 top
U15 "RS724XQ" TSSOP-14_L5.0-W4.4-P0.65-LS6.4-BL -1.983,-10.676 r270 top
U16 "G2061Q" QFN-24_L4.0-W4.0-P0.50-TL-EP2.7 -5.01,0.071 r180 top
X1 "8MHz" CRYSTAL-SMD_4P-L3.2-W2.5-BL 16.65,9.113 r180 top

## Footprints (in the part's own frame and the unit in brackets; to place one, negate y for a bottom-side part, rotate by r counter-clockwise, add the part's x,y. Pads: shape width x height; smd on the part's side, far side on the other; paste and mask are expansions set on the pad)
1206R [mm]
  rect 1.208x1.701 smd paste-100 mask+0.051: 1(-1.479,0) 2(1.479,0)
  silkscreen extent -2.31,-1.08 2.31,1.08, body extent -1.48,-0.8 1.82,0.8, height 0.6
C0402 [mm]
  rect 0.79x0.54 smd paste-100 mask+0.051: 1(-0.545,0) 2(0.545,0)
  silkscreen extent -1.17,-0.5 1.17,0.5, body extent -0.73,-0.27 0.73,0.28, height 0.6
C0603 [mm]
  rect 0.8x0.9 smd mask+0.102: 1(-0.7,0) 2(0.7,0)
  silkscreen extent -1.41,-0.71 1.39,0.72, body extent -0.8,-0.4 1,0.4, height 1
C0805 [mm]
  rect 1.41x1.35 smd paste-100 mask+0.051: 1(-1,0) 2(1,0)
  silkscreen extent -1.96,-0.9 1.96,0.9, body extent -1.1,-0.63 1.1,0.62, height 1.4
C1210 [mm]
  rect 1.635x2.7 smd paste-100 mask+0.051: 1(-1.517,0) 2(1.517,0)
  silkscreen extent -2.56,-1.58 2.56,1.58, body extent -1.4,-1.25 1.8,1.25, height 2.8
CRYSTAL-SMD_4P-L3.2-W2.5-BL [mm]
  rect 1.4x1.2 smd: 1(-1.1,-0.85) 2(1.1,-0.85) 3(1.1,0.85) 4(-1.1,0.85)
  silkscreen extent -2.26,-1.91 2.03,1.68, body extent -1.6,-1.25 1.6,1.25, height 0.8
ESOP-8_L4.9-W3.9-P1.27-LS6.0-BL-EP-2 [mm]
  oval 0.63x1.865 smd: 1(-1.905,-2.683) 2(-0.635,-2.683) 3(0.635,-2.683) 4(1.905,-2.683) 5(1.905,2.682) 6(0.635,2.682) 7(-0.635,2.682) 8(-1.905,2.682)
  rect 3.15x2.26 smd paste+0 mask+0.05: 9(0,0)
  silkscreen extent -2.82,-2.83 2.58,1.52, body extent -2.5,-1.94 2.49,1.94, height 1.7
GD32G553MEY7TR [mm]
  round 0.216 smd paste-100 mask+0.051: A1(0.4,3.6) A2(0.8,3.6) A3(1.2,3.6) A4(1.6,3.6) A5(2,3.6) A6(2.4,3.6) A7(2.8,3.6) A8(3.2,3.6) A9(3.6,3.6) B1(0.4,3.2) B2(0.8,3.2) B3(1.2,3.2) B4(1.6,3.2) B5(2,3.2) B6(2.4,3.2) B7(2.8,3.2) B8(3.2,3.2) B9(3.6,3.2) C1(0.4,2.8) C2(0.8,2.8) C3(1.2,2.8) C4(1.6,2.8) C5(2,2.8) C6(2.4,2.8) C7(2.8,2.8) C8(3.2,2.8) C9(3.6,2.8) D1(0.4,2.4) D2(0.8,2.4) D3(1.2,2.4) D4(1.6,2.4) D5(2,2.4) D6(2.4,2.4) D7(2.8,2.4) D8(3.2,2.4) D9(3.6,2.4) E1(0.4,2) E2(0.8,2) E3(1.2,2) E4(1.6,2) E5(2,2) E6(2.4,2) E7(2.8,2) E8(3.2,2) E9(3.6,2) F1(0.4,1.6) F2(0.8,1.6) F3(1.2,1.6) F4(1.6,1.6) F5(2,1.6) F6(2.4,1.6) F7(2.8,1.6) F8(3.2,1.6) F9(3.6,1.6) G1(0.4,1.2) G2(0.8,1.2) G3(1.2,1.2) G4(1.6,1.2) G5(2,1.2) G6(2.4,1.2) G7(2.8,1.2) G8(3.2,1.2) G9(3.6,1.2) H1(0.4,0.8) H2(0.8,0.8) H3(1.2,0.8) H4(1.6,0.8) H5(2,0.8) H6(2.4,0.8) H7(2.8,0.8) H8(3.2,0.8) H9(3.6,0.8) J1(0.4,0.4) J2(0.8,0.4) J3(1.2,0.4) J4(1.6,0.4) J5(2,0.4) J6(2.4,0.4) J7(2.8,0.4) J8(3.2,0.4) J9(3.6,0.4)
  silkscreen extent 0,0 4,4.25
IND-SMD_L2.5-W2.1 [mm]
  rect 0.85x2.1 smd: 1(-0.825,0) 2(0.825,0)
  silkscreen extent -1.25,-1.3 1.25,1.3, body extent -1.25,-1.05 1.25,1.05, height 1.25
IND-SMD_L4.0-W4.0 [mm]
  rect 1.6x3.5 smd: 1(-1.6,0) 2(1.6,0)
  silkscreen extent -2.08,-2.1 2.08,2.1, body extent -2,-2 2,2, height 1.8
MSOP-8_L3.0-W3.0-P0.65-LS5.0-BL [mm]
  oval 0.364x1.692 smd: 1(-0.975,-2.146) 2(-0.325,-2.146) 3(0.325,-2.146) 4(0.975,-2.146) 5(0.975,2.146) 6(0.325,2.146) 7(-0.325,2.146) 8(-0.975,2.146)
  silkscreen extent -1.76,-2.3 1.66,1.73, body extent -1.52,-1.52 1.52,1.52, height 1.7
POWERPAIR-8_L3.3-W3.3-P0.65-BL_SIZ260DT-T1-GE3 [mm]
  rect 0.45x0.45 smd paste+0 mask+0.05: 1(-0.975,-1.555) 2(-0.325,-1.555) 3(0.325,-1.555) 4(0.975,-1.555) 5(0.975,1.555) 6(0.325,1.555) 7(-0.325,1.555) 8(-0.975,1.555)
  rect 2.7x0.91 smd paste+0 mask+0.05: 9(0,0.555)
  rect 2.7x0.84 smd paste+0 mask+0.05: 10(0,-0.671)
  silkscreen extent -1.65,-2.17 1.65,1.65, body extent -1.65,-1.65 1.65,1.65, height 0.8
QFN-24_L4.0-W4.0-P0.50-TL-EP2.7 [mm]
  rect 0.633x0.28 smd paste-100 mask+0.051: 1(-1.912,1.25) 2(-1.912,0.75) 3(-1.912,0.25) 4(-1.912,-0.25) 5(-1.912,-0.75) 6(-1.912,-1.25) 13(1.912,-1.25) 14(1.912,-0.75) 15(1.912,-0.25) 16(1.912,0.25) 17(1.912,0.75) 18(1.912,1.25)
  rect 0.28x0.633 smd paste-100 mask+0.051: 7(-1.25,-1.912) 8(-0.75,-1.912) 9(-0.25,-1.912) 10(0.25,-1.912) 11(0.75,-1.912) 12(1.25,-1.912) 19(1.25,1.912) 20(0.75,1.912) 21(0.25,1.912) 22(-0.25,1.912) 23(-0.75,1.912) 24(-1.25,1.912)
  rect 2.7x2.7 smd paste-100 mask+0.051: 25(0,0)
  silkscreen extent -2.42,-2.08 2.08,2.08, body extent -2.01,-2.02 2.03,2.04, height 0.9
R0402 [mm]
  rect 0.566x0.54 smd paste-100 mask+0.051: 1(-0.433,0) 2(0.433,0)
  silkscreen extent -0.94,-0.5 0.94,0.5, body extent -0.5,-0.25 0.5,0.25, height 0.6
R0603 [mm]
  rect 0.806x0.864 smd paste-100 mask+0.051: 1(-0.753,0) 2(0.753,0)
  silkscreen extent -1.39,-0.66 1.39,0.66, body extent -0.75,-0.4 0.85,0.4, height 0.5
R1206 [mm]
  rect 1.208x1.701 smd paste-100 mask+0.051: 1(-1.479,0) 2(1.479,0)
  silkscreen extent -2.31,-1.08 2.31,1.08, body extent -1.48,-0.8 1.82,0.8, height 0.6
SMA_L4.3-W2.6-LS5.1-RD [mm]
  rect 2x2 smd: 1(-2.2,0) 2(2.2,0)
  silkscreen extent -2.98,-1.5 2.6,1.5, body extent -2.16,-1.3 2.16,1.3, height 2.3
SOD-123_L2.8-W1.8-LS3.7-RD [mm]
  rect 0.95x1.15 smd: 1(-1.692,0) 2(1.692,0)
  silkscreen extent -1.58,-0.87 1.41,0.87, body extent -1.4,-0.9 1.4,0.9, height 1.35
SOP-8_L4.9-W3.9-P1.27-LS6.0-BL [mm]
  oval 0.63x1.865 smd: 1(-1.905,-2.683) 2(-0.635,-2.682) 3(0.635,-2.682) 4(1.905,-2.682) 5(1.905,2.682) 6(0.635,2.682) 7(-0.635,2.682) 8(-1.905,2.682)
  silkscreen extent -2.5,-1.5 2.5,1.48, body extent -2.46,-1.96 2.46,1.98, height 0.9
SOT-23-5_L3.0-W1.7-P0.95-LS2.8-BR [mm]
  rect 1.1x0.6 smd: 1(1.3,-0.95) 2(1.3,0) 3(1.3,0.95) 4(-1.3,0.95) 5(-1.3,-0.95)
  silkscreen extent -0.9,-1.78 1.65,1.55, body extent -0.8,-1.46 0.8,1.46, height 1.25
TSOT-23-6_L2.9-W1.6-P0.95-LS2.8-BL [mm]
  rect 0.55x1.2 smd: 1(-0.95,-1.2) 2(0,-1.2) 3(0.95,-1.2) 4(0.95,1.2) 5(0,1.2) 6(-0.95,1.2)
  silkscreen extent -1.5,-2.25 1.5,0.8, body extent -1.5,-0.81 1.4,0.8, height 1.1
TSSOP-14_L5.0-W4.4-P0.65-LS6.4-BL [mm]
  rect 0.4x1.7 smd: 1(-1.95,-2.8) 2(-1.3,-2.8) 3(-0.65,-2.8) 4(0,-2.8) 5(0.65,-2.8) 6(1.3,-2.8) 7(1.95,-2.8) 8(1.95,2.8) 9(1.3,2.8) 10(0.65,2.8) 11(0,2.8) 12(-0.65,2.8) 13(-1.3,2.8) 14(-1.95,2.8)
  silkscreen extent -2.51,-1.74 2.5,1.74, body extent -2.51,-2.2 2.49,2.19, height 1.2
TSSOP-20_L6.5-W4.4-P0.65-LS6.4-BL [mm]
  oval 0.364x1.742 smd: 1(-2.925,-2.871) 2(-2.275,-2.871) 3(-1.625,-2.871) 4(-0.975,-2.871) 5(-0.325,-2.871) 6(0.325,-2.871) 7(0.975,-2.871) 8(1.625,-2.871) 9(2.275,-2.871) 10(2.925,-2.871) 11(2.925,2.871) 12(2.275,2.871) 13(1.625,2.871) 14(0.975,2.871) 15(0.325,2.871) 16(-0.325,2.871) 17(-0.975,2.871) 18(-1.625,2.871) 19(-2.275,2.871) 20(-2.925,2.871)
  silkscreen extent -3.71,-3.02 3.33,1.77, body extent -3.26,-2.19 3.25,2.2, height 2.65

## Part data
C1 C2 C11 C15 C18 C23 C25 C28 C31 C32 C33 C34 C35 C36 C37 C38 C39 C40 C41 C43 C46 C49 C53 C56 C59: library part CC0402KRX7R9BB104, "容值:100nF;精度:±10%;额定电压:50V;材质(温度系数):X7R;", JLCPCB Part Class=扩展库, LCSC Part Name="100nF ±10% 50V", Manufacturer=YAGEO(国巨), Temperature Coefficient=X7R, Tolerance=±10%, Voltage Rated=50V
C3 C4 C16 C17: library part 0805X106K250NT, "容值:10uF;精度:±10%;额定电压:25V;材质(温度系数):X5R;", JLCPCB Part Class=扩展库, LCSC Part Name="10uF ±10% 25V", Manufacturer=FH(风华), Temperature Coefficient=X5R, Tolerance=±10%, Voltage Rated=25V
C5 C6 C69 C70 C71 C106 C107 C108: library part C1210X7R106K101NT, "容值:10uF;额定电压:100V;温度系数:-;", JLCPCB Part Class=扩展库, LCSC Part Name="10uF ±10% 100V", Manufacturer=SANYEAR(叁叶源), Temperature Coefficient=-, Voltage Rated=100V
C7: library part CC0603KRX7R0BB104, "容值:100nF;精度:±10%;额定电压:100V;材质(温度系数):X7R;", JLCPCB Part Class=扩展库, LCSC Part Name="100nF ±10% 100V", Manufacturer=YAGEO(国巨), Temperature Coefficient=X7R, Tolerance=±10%, Voltage Rated=100V
C8: library part CC0402KRX7R9BB221, "容值:220pF;精度:±10%;额定电压:50V;材质(温度系数):X7R;", JLCPCB Part Class=扩展库, LCSC Part Name="220pF ±10% 50V", Manufacturer=YAGEO(国巨), Temperature Coefficient=X7R, Tolerance=±10%, Voltage Rated=50V
C10 C99 C100 C101 C102 C116 C117: library part CC0402KRX7R9BB102, "容值:1nF;精度:±10%;额定电压:50V;材质(温度系数):X7R;", JLCPCB Part Class=扩展库, LCSC Part Name="1nF ±10% 50V", Manufacturer=YAGEO(国巨), Temperature Coefficient=X7R, Tolerance=±10%, Voltage Rated=50V
C12 C13 C14 C19 C20 C21 C22: library part CC0603KRX5R6BB106, "容值:10uF;精度:±10%;额定电压:10V;材质(温度系数):X5R;", JLCPCB Part Class=扩展库, LCSC Part Name="10uF ±10% 10V", Manufacturer=YAGEO(国巨), Temperature Coefficient=X5R, Tolerance=±10%, Voltage Rated=10V
C24 C27 C60 C61 C62 C63 C64 C65: library part 0402CG200J500NT, "容值:20pF;精度:±5%;额定电压:50V;材质(温度系数):C0G;", JLCPCB Part Class=基础库, LCSC Part Name="20pF ±5% 50V", Manufacturer=FH(风华), Temperature Coefficient=C0G, Tolerance=±5%, Voltage Rated=50V
C26 C29 C30 C44 C45 C47 C48 C50 C51 C90 C111 C112 C113 C114 C115: library part 0402CG101J500NT, "容值:100pF;精度:±5%;额定电压:50V;材质(温度系数):C0G;", JLCPCB Part Class=基础库, LCSC Part Name="100pF ±5% 50V", Manufacturer=FH(风华), Temperature Coefficient=C0G, Tolerance=±5%, Voltage Rated=50V
C42: library part CC0402KRX7R9BB104, "容值:100nF;精度:±10%;额定电压:50V;材质(温度系数):X7R;", JLCPCB Part Class="Extended Part", LCSC Part Name="100nF ±10% 50V", Manufacturer=YAGEO(国巨), Temperature Coefficient=X7R, Tolerance=±10%, Voltage Rated=50V
C52 C54: library part CC0402KRX5R6BB225, "容值:2.2uF;精度:±10%;额定电压:10V;材质(温度系数):X5R;", JLCPCB Part Class=扩展库, LCSC Part Name="2.2uF ±10% 10V", Manufacturer=YAGEO(国巨), Temperature Coefficient=X5R, Tolerance=±10%, Voltage Rated=10V
C103 C104 C105 C110: library part GRM155R61H224KE01D, "容值:220nF;精度:±10%;额定电压:50V;材质(温度系数):X5R;", JLCPCB Part Class=扩展库, LCSC Part Name="220nF ±10% 50V", Manufacturer=muRata(村田), Temperature Coefficient=X5R, Tolerance=±10%, Voltage Rated=50V
D1: library part US1D_C2848672, "二极管配置:独立式;正向压降(Vf):1V@1A;直流反向耐压(Vr):200V;平均整流电流(Io):1A;反向恢复时间(trr):75ns;", Average Rectified Current (Io)=1A, Forward Voltage (Vf@If)=1V@1A, JLCPCB Part Class=扩展库, LCSC Part Name="电压:200V 电流:1A", Manufacturer=GOODWORK(固得沃克), Operating Temperature=-50℃~+150℃@(Tj), Reverse Leakage Current=5uA@200V, Reverse Voltage (Vr)=200V
D8 D9 D10 D11: "二极管配置:独立式;正向压降(Vf):1V@1A;直流反向耐压(Vr):200V;整流电流:1A;反向恢复时间(trr):35ns;", Forward Voltage (Vf@If)=1V@1A, JLCPCB Part Class=扩展库, LCSC Part Name="电压:200V 电流:1A", Manufacturer=MDD(辰达半导体), Operating Temperature=-55℃~+150℃@(Tj), Rectified Current=1A, Reverse Leakage Current=5uA@200V, Reverse Voltage (Vr)=200V
L1: library part PRS4018-100MT, DC Resistance (DCR)=234mΩ, JLCPCB Part Class="Extended Part", LCSC Part Name="10uH ±20%", Manufacturer=FH(风华), Rated Current=840mA, Tolerance=±20%
L2: library part PRS2512-4R7MT, "电感值:4.7uH;精度:±20%;额定电流:840mA;", DC Resistance (DCR)=273mΩ, JLCPCB Part Class=扩展库, LCSC Part Name="4.7uH ±20% 840mA 273mΩ", Manufacturer=FH(风华), Rated Current=840mA, Tolerance=±20%
Q1 Q2 Q3: JLCPCB Part Class=扩展库, Manufacturer=VISHAY(威世)
R1 R3 R8: library part 0402WGF2003TCE, "电阻类型:厚膜电阻;阻值:200kΩ;精度:±1%;功率:62.5mW;最大工作电压:50V;温度系数:±100ppm/℃;", JLCPCB Part Class=基础库, LCSC Part Name="200kΩ ±1% 62.5mW 厚膜电阻", Manufacturer=UNI-ROYAL(厚声), Operating Temperature Range=-55℃~+155℃, Overload Voltage (Max)=50V, Power(Watts)=62.5mW, Temperature Coefficient=±100ppm/℃, Tolerance=±1%
R2: library part 0402WGF4702TCE, "电阻类型:厚膜电阻;阻值:47kΩ;精度:±1%;功率:62.5mW;最大工作电压:50V;温度系数:±100ppm/℃;", JLCPCB Part Class=基础库, LCSC Part Name="47kΩ ±1% 62.5mW 厚膜电阻", Manufacturer=UNI-ROYAL(厚声), Operating Temperature Range=-55℃~+155℃, Overload Voltage (Max)=50V, Power(Watts)=62.5mW, Temperature Coefficient=±100ppm/℃, Tolerance=±1%
R4 R6 R7 R10 R11 R12 R31 R40 R47 R48 R53 R88 R89 R97 R100 R101 R108 R116 R118 R120 R122 R140 R142: library part 0402WGF1002TCE, "电阻类型:厚膜电阻;阻值:10kΩ;精度:±1%;功率:62.5mW;最大工作电压:50V;温度系数:±100ppm/℃;", JLCPCB Part Class=基础库, LCSC Part Name="10kΩ ±1% 62.5mW 厚膜电阻", Manufacturer=UNI-ROYAL(厚声), Operating Temperature Range=-55℃~+155℃, Overload Voltage (Max)=50V, Power(Watts)=62.5mW, Temperature Coefficient=±100ppm/℃, Tolerance=±1%
R5: library part 0402WGF1203TCE, "电阻类型:厚膜电阻;阻值:120kΩ;精度:±1%;功率:62.5mW;最大工作电压:50V;温度系数:±100ppm/℃;", JLCPCB Part Class=扩展库, LCSC Part Name="120kΩ ±1% 62.5mW 厚膜电阻", Manufacturer=UNI-ROYAL(厚声), Operating Temperature Range=-55℃~+155℃, Overload Voltage (Max)=50V, Power(Watts)=62.5mW, Temperature Coefficient=±100ppm/℃, Tolerance=±1%
R9: library part RC0402FR-0730KL, "电阻类型:厚膜电阻;阻值:30kΩ;精度:±1%;功率:62.5mW;最大工作电压:50V;温度系数:±100ppm/℃;", JLCPCB Part Class=扩展库, LCSC Part Name="厚膜电阻 30kΩ ±1% 62.5mW", Manufacturer=YAGEO(国巨), Operating Temperature Range=-55℃~+155℃, Overload Voltage (Max)=50V, Power(Watts)=62.5mW, Temperature Coefficient=±100ppm/℃, Tolerance=±1%
R13 R14 R17 R32 R33 R35 R36 R37 R38 R39 R43 R44 R46: library part 0402WGF5101TCE, "电阻类型:厚膜电阻;阻值:5.1kΩ;精度:±1%;功率:62.5mW;最大工作电压:50V;温度系数:±100ppm/℃;", JLCPCB Part Class="Basic Part", LCSC Part Name="5.1kΩ ±1% 62.5mW 厚膜电阻", Manufacturer=UNI-ROYAL(厚声), Operating Temperature Range=-55℃~+155℃, Overload Voltage (Max)=50V, Power(Watts)=62.5mW, Temperature Coefficient=±100ppm/℃, Tolerance=±1%
R15 R16 R24 R25 R26 R27 R28 R29 R30 R52 R77 R78 R136 R137: library part 0402WGF2001TCE, "电阻类型:厚膜电阻;阻值:2kΩ;精度:±1%;功率:62.5mW;最大工作电压:50V;温度系数:±100ppm/℃;", JLCPCB Part Class="Basic Part", LCSC Part Name="2kΩ ±1% 62.5mW 厚膜电阻", Manufacturer=UNI-ROYAL(厚声), Operating Temperature Range=-55℃~+155℃, Overload Voltage (Max)=50V, Power(Watts)=62.5mW, Temperature Coefficient=±100ppm/℃, Tolerance=±1%
R18 R19 R20 R21 R22 R23: library part 0402WGF1002TCE, "电阻类型:厚膜电阻;阻值:10kΩ;精度:±1%;功率:62.5mW;最大工作电压:50V;温度系数:±100ppm/℃;", JLCPCB Part Class="Basic Part", LCSC Part Name="10kΩ ±1% 62.5mW 厚膜电阻", Manufacturer=UNI-ROYAL(厚声), Operating Temperature Range=-55℃~+155℃, Overload Voltage (Max)=50V, Power(Watts)=62.5mW, Temperature Coefficient=±100ppm/℃, Tolerance=±1%
R34 R42: library part Res2, "Resistor"
R41: library part 0402WGF5232TCE, "电阻类型:厚膜电阻;阻值:52.3kΩ;精度:±1%;功率:62.5mW;最大工作电压:50V;温度系数:±100ppm/℃;", JLCPCB Part Class=扩展库, LCSC Part Name="52.3kΩ ±1% 62.5mW 厚膜电阻", Manufacturer=UNI-ROYAL(厚声), Operating Temperature Range=-55℃~+155℃, Overload Voltage (Max)=50V, Power(Watts)=62.5mW, Temperature Coefficient=±100ppm/℃, Tolerance=±1%
R45 R50: library part 0603WAF1802T5E, "电阻类型:厚膜电阻;阻值:18kΩ;精度:±1%;功率:100mW;最大工作电压:75V;温度系数:±100ppm/℃;", JLCPCB Part Class=基础库, LCSC Part Name="18kΩ ±1% 100mW 厚膜电阻", Manufacturer=UNI-ROYAL(厚声), Operating Temperature Range=-55℃~+155℃, Overload Voltage (Max)=75V, Power(Watts)=100mW, Temperature Coefficient=±100ppm/℃, Tolerance=±1%
R49 R90 R111: library part RLM12FTCMR050, "电阻类型:采样电阻;阻值:50mΩ;精度:±1%;额定压降:-;功率:1W;安装方式:贴片;", JLCPCB Part Class=扩展库, LCSC Part Name="50mΩ ±1% 1W", Manufacturer=大毅科技, Power(Watts)=1W, Rated Current=-, Tolerance=±1%
R51: "阻值(25℃):10kΩ;B值(25℃/50℃):3380K;电阻精度:±1%;功率:100mW;B值精度:±1%;最大稳态电流(25℃):310uA;", B Constant Tolerance=±1%, JLCPCB Part Class=扩展库, LCSC Part Name="10kΩ 电阻精度:±1% 3380K", Manufacturer=TDK, Operating Temperature=-40℃~+125℃, Power=100mW, Resistance @ 25℃=10kΩ, Steady State Current (Max)=310uA
R54: library part 0603WAF2001T5E, "电阻类型:厚膜电阻;阻值:2kΩ;精度:±1%;功率:100mW;最大工作电压:75V;温度系数:±100ppm/℃;", JLCPCB Part Class=基础库, LCSC Part Name="2kΩ ±1% 100mW 厚膜电阻", Manufacturer=UNI-ROYAL(厚声), Operating Temperature Range=-55℃~+155℃, Overload Voltage (Max)=75V, Power(Watts)=100mW, Temperature Coefficient=±100ppm/℃, Tolerance=±1%
R64 R65 R66 R73 R74 R75: library part 0402WGF1302TCE, "电阻类型:厚膜电阻;阻值:13kΩ;精度:±1%;功率:62.5mW;最大工作电压:50V;温度系数:±100ppm/℃;", JLCPCB Part Class=扩展库, LCSC Part Name="13kΩ ±1% 62.5mW 厚膜电阻", Manufacturer=UNI-ROYAL(厚声), Operating Temperature Range=-55℃~+155℃, Overload Voltage (Max)=50V, Power(Watts)=62.5mW, Temperature Coefficient=±100ppm/℃, Tolerance=±1%
R67 R68 R69 R70 R71 R72 R76 R79: library part 0402WGF1001TCE, "电阻类型:厚膜电阻;阻值:1kΩ;精度:±1%;功率:62.5mW;最大工作电压:50V;温度系数:±100ppm/℃;", JLCPCB Part Class=基础库, LCSC Part Name="1kΩ ±1% 62.5mW 厚膜电阻", Manufacturer=UNI-ROYAL(厚声), Operating Temperature Range=-55℃~+155℃, Overload Voltage (Max)=50V, Power(Watts)=62.5mW, Temperature Coefficient=±100ppm/℃, Tolerance=±1%
R115 R117 R119 R121 R123 R144: library part 0402WGF1000TCE, "电阻类型:厚膜电阻;阻值:100Ω;精度:±1%;功率:62.5mW;最大工作电压:50V;温度系数:±200ppm/℃;", JLCPCB Part Class=基础库, LCSC Part Name="100Ω ±1% 62.5mW 厚膜电阻", Manufacturer=UNI-ROYAL(厚声), Operating Temperature Range=-55℃~+155℃, Overload Voltage (Max)=50V, Power(Watts)=62.5mW, Temperature Coefficient=±200ppm/℃, Tolerance=±1%
R124: library part 0402WGF2502TCE, "电阻类型:厚膜电阻;阻值:25kΩ;精度:±1%;功率:62.5mW;最大工作电压:50V;温度系数:±100ppm/℃;", JLCPCB Part Class=扩展库, LCSC Part Name="25kΩ ±1% 62.5mW 厚膜电阻", Manufacturer=UNI-ROYAL(厚声), Operating Temperature Range=-55℃~+155℃, Overload Voltage (Max)=50V, Power(Watts)=62.5mW, Temperature Coefficient=±100ppm/℃, Tolerance=±1%
R130 R131 R132 R133 R134 R135 R141 R143 R145: library part FRC0603F7R50TS, "电阻类型:厚膜电阻;阻值:7.5Ω;精度:±1%;功率:100mW;最大工作电压:75V;温度系数:±200ppm/℃;", JLCPCB Part Class=扩展库, LCSC Part Name="7.5Ω ±1% 100mW 厚膜电阻", Manufacturer=FOJAN(富捷), Overload Voltage (Max)=75V, Power(Watts)=100mW, Temperature Coefficient=±200ppm/℃, Tolerance=±1%
U1: "电源IC", JLCPCB Part Class=扩展库, Manufacturer=SCT(芯洲科技)
U3: JLCPCB Part Class=扩展库, Manufacturer=SCT(芯洲科技)
U4: library part XC6219B332MR_C347386, "输出类型:固定;最大输入电压:7V;输出电压:3.3V;输出电流:300mA;电源纹波抑制比(PSRR):40dB@(1kHz);输出极性:正极;", Dropout Voltage=280mV@(100mA), JLCPCB Part Class=扩展库, LCSC Part Name="输入7V 输出3.3V 300mA", Manufacturer=UMW(友台半导体), Maximum Input Voltage=7V, Operating Temperature=-20℃~+60℃, Output Current=300mA, Output Voltage=3.3V, Power Supply Rejection Ratio (PSRR)=40dB@(1kHz)
U6: JLCPCB Part Class=扩展库, Manufacturer=HGSEMI(华冠)
U7: "类型:收发器;数据速率:12Mbps;驱动器/接收器:1/1;", JLCPCB Part Class=扩展库, LCSC Part Name="3.3V供电 12Mbps 收发器", Manufacturer=SIT(芯力特), Operating Temperature=-40℃~+85℃, Supply Voltage=3V~3.6V
U8: "输入类型:-;电源电压:2V~6V;灌电流(IOL):7.8mA;拉电流(IOH):7.8mA;", JLCPCB Part Class=扩展库, Manufacturer=I-CORE(中微爱芯), Operating Temperature=-40℃~+85℃, Sink Current=7.8mA, Supply Voltage=2V~6V
U15: "放大器数:四路;增益带宽积(GBP):10MHz;输入偏置电流(Ib):1pA;压摆率(SR):7V/us;带宽(-3db):-;轨到轨:-;", Current - Input Bias(Ib)=1pA, JLCPCB Part Class=扩展库, LCSC Part Name=低噪声运放RS724XQ, Manufacturer=RUNIC(润石), Operating Temperature=-40℃~+125℃, Output Current=70mA
U16: "驱动通道数:6;峰值灌电流:1.8A;峰值拉电流:1.5A;电源电压:8V~20V;上升时间:30ns;下降时间:30ns;是否隔离:非隔离;", JLCPCB Part Class=扩展库, Manufacturer=WXNSIC(国硅集成), Operating Temperature=-40℃~+125℃, Peak Output Current(sink)=1.8A, Peak Output Current(source)=1.5A, Supply Voltage=8V~20V
X1: library part X32258MSB4SI, "晶振类型:贴片晶振;频率:8MHz;常温频差:±10ppm;外接负载电容:20pF;频率稳定度(全温):±20ppm;", External load capacitor=20pF, Frequency Stability(Full temperature range)=±20ppm, JLCPCB Part Class=扩展库, LCSC Part Name="8MHz ±10ppm 20pF", Manufacturer=YXC(扬兴晶振), Normal temperature Frequency Tolerance=±10ppm, Operating Temperature=-40℃~+85℃

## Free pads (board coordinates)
  round 1 smd far side: 1(-18.632,16.467) 1(-18.116,-15.316) 1(11.107,-21.753) 1(17.656,17.488)
  round 1 smd: 1(-17.844,16.493) 1(-17.329,-15.29) 1(11.894,-21.727) 1(18.443,17.514)
  round 1.2 hole 0.8: 1(25.241,-2.512) 1(25.347,-0.542) 2(25.271,1.457) 3(25.013,3.381) 5(24.65,5.274) 6(24.186,7.018) 9(23.372,-9.09) 10(-7.597,-23.56) 10(-7.597,-21.724) 10(22.536,-10.998) 11(18.867,-16.232) 12(-5.057,-18.341) 12(-5.057,-16.503) 12(17.59,-17.626) 12(20.039,-14.871) 12(21.552,-12.932)
  round 2 hole 1.2: 9(-23.648,-8.157) 9(-23.648,-0.579) 9(-23.648,7.116)
  round 2 hole 1.5: 13(-9.621,18.815) 13(-9.621,21.381) 13(-4.088,22.367) 13(-4.088,24.679)
  round 4.5 / inner round 2.5 / far side round 4.5 hole 2: 15(-14.06,-18.638) 15(-14.06,18.638) 15(14.06,-18.638) 15(14.06,18.638)

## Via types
v1: diameter 0.457, hole 0.254, Top Layer to Bottom Layer, tented both sides, 394 vias
v2: diameter 0.203, hole 0.102, Top Layer to Bottom Layer, tented both sides, 43 vias

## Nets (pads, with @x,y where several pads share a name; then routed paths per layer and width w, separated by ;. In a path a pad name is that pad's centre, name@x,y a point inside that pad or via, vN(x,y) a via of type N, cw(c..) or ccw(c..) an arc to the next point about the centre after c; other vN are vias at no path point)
3.3V: C13.2 C14.2 C23.2 C25.2 C28.2 C35.1 C36.1 C37.1 C38.1 C39.1 C40.1 C41.1 C43.2 C45.1 C46.2 C48.1 C49.2 C51.1 C52.1 C53.2 C54.1 C59.2 D11.1 pad.1@25.347,-0.542 R6.2 R7.2 R11.1 R13.2 R14.1 R31.2 R35.1 R36.1 R37.2 R38.1 R44.1 R46.2 R47.2 R48.1 R53.2 R78.1 U2.8 U4.5 U5.A1 U5.A9 U5.B9 U5.E1 U5.J1 U5.J5 U5.J6 U5.J9 U6.8 U7.8 U8.1 U8.2 U8.3 U8.20 U9.8 U15.4 | length 55.2
  Top Layer w0.203: v1(8.599,-9.714) R13.2@9.423,-9.714 ; v1(8.605,-6.72) R14.1@9.43,-6.72
  Top Layer w0.254: U2.8@-0.162,-18.308 v1(1.118,-18.308) ; U5.A9@14.173,5.115 v2(14.573,5.115) ; v2(17.373,5.115) 17.556,5.115
  Top Layer w0.305: U15.4@-4.783,-10.676 v1(-3.171,-10.676) ; U9.8@-0.207,-23.859 v1(1.044,-23.859) ; R37.2@6.626,-17.656 v1(7.447,-17.656) ; U8.1@8.862,-0.939 v1(10.125,-0.939) ; U8.2@8.862,-0.289 v1(7.548,-0.289) 7.548,0.056 7.854,0.361 U8.3@8.862,0.361 ; C25.2@9.442,-12.084 10.061,-12.084 10.216,-11.928 10.216,-11.673 v1(10.512,-11.377) U6.8@11.888,-11.377 ; D11.1@10.62,10.519 v1(11.583,10.519) ; v1(10.866,2.25) R47.2@11.579,2.25 R6.2@11.579,3.248 ; v1(10.866,6.487) R31.2@11.579,6.487 R53.2@11.579,5.324 ; C38.1@13.861,0.668 13.861,1.603 v2(14.173,1.915) ; v1(15.037,-1.316) R7.2@15.037,-0.183 ; v2(15.773,1.915) 15.773,1.115 C40.1@16.22,0.668 ; v2(17.373,1.915) 17.373,0.691 C36.1@17.396,0.668 ; v2(17.373,3.515) U5.J6@17.373,3.915 ; 17.556,5.115 17.947,4.724 C35.1@18.476,4.724 C39.1@19.635,4.724 ; U7.8@23.012,-3.979 23.599,-3.979 v1(24.005,-4.385)
  Top Layer w0.381: v1(-4.038,-15.577) C48.1@-3.263,-15.577 ; C51.1@-3.263,-20.703 -2.112,-20.703 R44.1@-2.022,-20.793 v1(-1.214,-20.793) ; R38.1@-2.022,-15.695 v1(-1.308,-15.695) ; U8.20@3.12,-0.939 4.177,-0.939 v1(4.424,-1.185) ; R46.2@11.942,-3.348 v1(11.942,-2.354) ; R48.1@14.25,-3.343 v1(14.25,-2.348) ; v1(21.048,2.618) R11.1@21.79,2.618
  Bottom Layer w0.254: v2(17.373,5.115) 17.556,5.115
  Bottom Layer w0.305: v1(10.866,6.487) 10.91,6.443 C41.1@11.774,6.443 ; C37.1@14.952,-0.422 15.037,-0.508 v1(15.037,-1.316) ; 17.556,5.115 17.947,4.724 C23.2@18.476,4.724 C52.1@19.635,4.724 ; C53.2@18.476,3.245 C54.1@19.638,3.245 v1(20.328,3.936) ; v1(18.865,-7.406) C45.1@19.698,-7.406 19.797,-7.307 R36.1@19.797,-6.211 ; v1(21.045,-1.019) R35.1@21.045,-0.283 ; C43.2@23.181,-4.385 v1(24.005,-4.385)
  Bottom Layer w0.381: C59.2@-5.125,-10.494 -4.959,-10.66 R78.1@-3.989,-10.66 -3.973,-10.676 v1(-3.171,-10.676) ; C49.2@-0.174,-23.4 0.586,-23.4 v1(1.044,-23.859) ; C46.2@-0.159,-18.045 0.855,-18.045 v1(1.118,-18.308) ; C28.2@3.611,-0.438 4.359,-1.185 v1(4.424,-1.185) 6.652,-1.185 v1(7.548,-0.289)
  other v1: 16.345,13.919 17.187,13.919 18.029,13.919 18.871,13.919 16.345,14.647 17.187,14.647 18.029,14.647 18.871,14.647 16.345,15.375 17.187,15.375 18.029,15.375 18.871,15.375
5V: C12.2 C18.1 C19.2 C20.2 C21.2 C22.2 L2.2 R41.2 U4.1 U4.3 | length 5.3
  Top Layer w0.381: v1(3.502,15.181) R41.2@3.502,15.984
  Bottom Layer w0.381: v1(3.502,15.181) 4.193,14.491 7.509,14.491 v1(7.631,14.612)
  other v1: 7.631,15.346 7.631,16.079 7.631,16.812 7.631,17.546 7.631,18.279 7.631,19.012 7.631,19.746 7.631,20.505 7.631,21.238
10.4V: C2.1 C3.1 C4.1 C15.1 C16.1 C17.1 C110.2 L1.2 R5.2 R8.2 R133.2 R134.2 R135.2 U3.3 U16.4 | length 6.5
  Top Layer w0.254: U16.4@-3.098,0.321 v1(-2.258,0.321)
  Top Layer w0.381: v1(-0.175,10.686) R5.2@-0.175,11.489 ; v1(4.68,15.178) R8.2@4.68,15.981
  Bottom Layer w0.381: R134.2@-9.996,1.878 v1(-9.216,2.659) ; R135.2@-9.407,3.699 v1(-8.588,3.699) ; R133.2@-7.234,-4.955 v1(-6.062,-4.955) ; C110.2@-2.978,0.796 -2.503,0.321 v1(-2.258,0.321)
  other v1: 2.347,20.831 2.347,21.533 2.347,22.236 1.645,22.938 2.347,22.938 1.645,23.666 2.347,23.666 2.347,24.368 2.347,25.07 2.347,25.773
/RESET: C42.2 R31.1 U5.D8 | length 5.1
  Top Layer w0.203: C42.2@12.538,7.656 12.444,7.562 R31.1@12.444,6.487 v1(13.187,6.487)
  Mid-Layer 3 w0.152: v1(13.187,6.487) 14.035,5.638 14.776,5.638 14.984,5.43 14.984,5.105 v2(15.373,4.715)
BOARDTEMP: C56.1 R29.1 R46.1 R51.2 | length 4.1
  Top Layer w0.203: v1(10.787,-5.187) 10.776,-5.177 R51.2@10.776,-4.225 11.931,-4.225 R46.1@11.942,-4.214 R29.1@13.094,-4.214
  Bottom Layer w0.203: v1(10.787,-5.187) C56.1@10.787,-4.331
BOARDTEMP_ARM: C33.1 R29.2 U5.F6 | length 11.7
  Top Layer w0.203: R29.2@13.094,-3.348 v1(13.094,-2.354)
  Bottom Layer w0.152: v1(13.094,-2.354) 13.094,1.71 12.719,2.085 12.719,3.484 13.015,3.78 14.304,3.78 14.503,3.581 15.435,3.581 15.769,3.915 v2(16.173,3.915)
  Bottom Layer w0.203: C33.1@13.102,-3.239 v1@13.102,-2.362
BOARDTYPE: R30.1 R48.2 R52.2 | length 3.3
  Top Layer w0.203: v1(14.26,-5.292) 14.25,-5.282 R48.2@14.25,-4.208 14.251,-4.21 R30.1@15.399,-4.21
  Bottom Layer w0.203: R52.2@14.25,-4.208 14.25,-5.282 v1(14.26,-5.292)
BOARDTYPE_ARM: C34.1 R30.2 U5.G6 | length 12
  Top Layer w0.203: R30.2@15.399,-3.344 v1(15.399,-2.35)
  Mid-Layer 3 w0.102: v2(16.573,3.915) 16.832,4.173 17.549,4.173
  Mid-Layer 3 w0.152: v1(15.399,-2.35) 15.926,-1.823 17.539,-1.823 18.237,-1.125 18.237,3.702 17.766,4.173 17.549,4.173
  Bottom Layer w0.203: v1(15.399,-2.35) 15.401,-2.352 C34.1@15.401,-3.227
DAC1: R15.1 U5.D6 | length 7.8
  Top Layer w0.203: v1(21.048,5.057) R15.1@21.79,5.057
  Mid-Layer 4 w0.152: v2(15.373,3.915) 15.373,4.32 15.881,4.827 16.268,4.827 16.938,5.497 17.729,5.497 18.485,4.741 20.732,4.741 v1(21.048,5.057)
DAC2: R16.1 U5.F7 | length 6.7
  Top Layer w0.203: v1(21.043,6.2) R16.1@21.786,6.2
  Mid-Layer 3 w0.102: v2(16.173,4.315) 16.173,4.789 16.465,5.081
  Mid-Layer 3 w0.152: 16.465,5.081 16.817,5.433 17.584,6.2 18.804,6.2 v1(21.043,6.2)
GND: C2.2 C3.2 C4.2 C5.2 C6.2 C7.1 C8.2 C12.1 C13.1 C14.1 C15.2 C16.2 C17.2 C18.2 C19.1 C20.1 C21.1 C22.1 C23.1 C24.2 C25.1 C26.1 C27.2 C28.1 C29.1 C30.1 C31.2 C32.2 C33.2 C34.2 C35.2 C36.2 C37.2 C38.2 C39.2 C40.2 C41.2 C42.1 C43.1 C44.2 C46.1 C47.2 C49.1 C50.2 C52.2 C53.1 C54.2 C56.2 C59.1 C69.2 C70.2 C71.2 C90.1 C99.1 C101.1 C106.2 C107.2 C108.2 C110.1 C111.1 C112.1 C113.1 C114.1 C115.1 C117.1 D1.2 pad.1@25.241,-2.512 pad.12@17.59,-17.626 pad.12@21.552,-12.932 pad.13@-4.088,22.367 pad.13@-4.088,24.679 R2.2 R3.1 R4.2 R9.2 R10.2 R12.1 R17.2 R18.2 R19.2 R20.2 R21.2 R22.2 R23.2 R32.2 R33.2 R39.2 R40.2 R43.2 R49.1 R51.1 R52.1 R54.1 R67.1 R68.1 R69.1 R77.1 R79.1 R90.1 R111.1 R116.1 R118.1 R120.1 R122.1 R124.1 R140.1 R142.1 U1.7 U1.9 U2.5 U3.1 U4.2 U5.A4 U5.A8 U5.B1 U5.C9 U5.D9 U5.F1 U5.H6 U5.H9 U5.J2 U6.1 U6.2 U6.3 U6.4 U6.7 U7.5 U8.10 U9.5 U15.11 U16.6 U16.25 X1.2 X1.4 | length 155.1
  Top Layer w0.203: R90.1@-14.257,-10.92 -15.182,-11.845 -15.182,-12.531 -14.997,-12.717 -11.461,-12.717 -10.969,-12.225 -10.969,-9.876 -10.653,-9.56 R67.1@-9.978,-9.56 ; U5.C9@14.973,5.115 v2(15.373,5.115) 15.373,6.15
  Top Layer w0.254: v1(-15.36,-4.465) -15.36,-3.124 -15.202,-2.966 R49.1@-14.257,-2.966 ; v1(-15.36,3.339) -15.36,4.681 -15.202,4.838 R111.1@-14.257,4.838 ; R90.1@-14.257,-10.92 R90.1@-14.257,-10.501 ; v1(-13.217,4.7) -12.999,4.482 C101.1@-12.225,4.482 ; v1(-12.045,-10.548) C117.1@-12.045,-9.652 ; U16.6@-3.098,1.321 v1(-2.258,1.321) ; v1(-1.178,0.362) C115.1@-0.506,0.362 ; v1(-1.174,1.97) C113.1@-0.503,1.97 ; v1(-1.174,4.555) C111.1@-0.503,4.555 ; U2.5@-0.162,-16.357 0.825,-16.357 1.118,-16.65 v1(1.118,-16.955) ; v2(16.973,5.115) 16.973,5.366
  Top Layer w0.305: U9.5@-0.207,-21.908 v1(1.044,-21.908) ; U15.11@0.817,-10.676 1.821,-10.676 v1(2.46,-11.315) ; v1(6.81,-23.365) R43.2@6.81,-22.553 ; v1(7.548,4.911) U8.10@8.862,4.911 ; C25.1@9.442,-10.993 9.904,-10.993 10.037,-10.86 10.037,-10.532 10.462,-10.107 v1(10.512,-10.107) U6.7@11.888,-10.107 ; v1(10.576,7.656) C42.1@11.448,7.656 ; v1(10.866,4.29) R10.2@11.579,4.29 ; C32.2@12.45,10.249 v1(12.45,11.119) ; v1(13.861,-1.316) C38.2@13.861,-0.422 ; v1(16.22,-1.263) C40.2@16.22,-0.422 ; 16.973,5.366 17.421,5.814 C35.2@18.476,5.814 C39.2@19.635,5.814 ; v1(17.396,-1.263) C36.2@17.396,-0.422
  Top Layer w0.381: v1(-11.989,11.21) R124.1@-11.989,11.863 ; R3.1@-10.825,10.67 v1(-10.171,10.67) ; v1(-9.126,-14.167) R77.1@-8.329,-14.167 ; v1(-5.684,-3.734) C90.1@-4.858,-3.734 ; v1(-5.431,-6.163) R116.1@-4.718,-6.163 ; v1(-5.315,14.463) -4.934,14.082 U1.7@-3.42,14.082 ; v1(-4.038,-19.155) C47.2@-3.263,-19.155 ; C50.2@-3.263,-24.687 -2.083,-24.687 R39.2@-2.022,-24.626 v1(-1.265,-24.626) ; v1(-2.221,-6.876) R120.1@-2.221,-6.163 ; R17.2@-2.022,-19.001 v1(-1.308,-19.001) ; C112.1@-1.244,-3.862 v1(-1.244,-3.15) ; C8.2@-0.037,12.706 0.628,12.041 v1(0.628,11.489) ; v1(0.285,-6.876) R140.1@0.285,-6.163 ; C114.1@1.241,-3.862 v1(1.241,-3.15) ; U4.2@9.136,13.465 v1(10.092,13.465) ; R51.1@10.776,-3.359 v1(10.776,-2.365) ; v1@12.443,-0.527 R18.2@12.443,0.261 R20.2@12.443,1.253 ; v1(15.928,-11.377) U6.1@17.253,-11.377 ; v1(15.928,-10.107) U6.2@17.253,-10.107 ; v1(15.928,-8.837) U6.3@17.253,-8.837 ; v1(15.928,-7.567) U6.4@17.253,-7.567 ; v1(21.048,3.851) R12.1@21.79,3.851 ; U7.5@21.061,-3.979 v1(21.061,-2.731)
  Top Layer w0.508: 14.275,9.963 X1.2@15.55,9.963 15.55,11.102 ; 17.751,7.164 X1.4@17.751,8.262 18.887,8.262
  Mid-Layer 4 w0.203: v1(-15.36,-4.465) -15.36,-4.811 -15.169,-5.002 -14.476,-5.002 -13.635,-5.843 -13.635,-7.94 -12.121,-9.455 -2.794,-9.455 v1(-2.476,-9.136) ; v1(-15.36,3.339) -15.36,3.936 -15.135,4.161 -14.454,4.161 -14.212,3.918 -14.212,2.266 -11.61,-0.336 -11.61,-2.233 -5.889,-7.954 -1.876,-7.954 0.14,-9.97 0.14,-12.875 -0.984,-13.998 -2.087,-13.998 v1(-2.476,-13.61)
  Bottom Layer w0.203: C33.2@13.102,-4.33 C33.2@13.194,-4.33 ; R52.1@14.25,-3.343 14.62,-3.343 14.773,-3.495 14.773,-3.702 15.388,-4.317 C34.2@15.401,-4.317
  Bottom Layer w0.254: v1(-12.462,-2.743) C99.1@-11.716,-2.743 ; C59.1@-5.125,-11.584 -5.125,-12.213 -4.949,-12.389 R79.1@-4.949,-12.861 v1(-4.949,-13.566) ; C110.1@-2.978,1.886 -2.437,1.886 -2.258,1.707 v1(-2.258,1.321) ; v1(-2.476,-13.61) R68.1@-1.707,-13.61 ; v1(-2.476,-9.136) R69.1@-1.707,-9.136 ; v1(0.643,-1.406) R142.1@0.643,-0.665 ; R122.1@0.643,2.923 v1(0.643,3.665) ; R118.1@0.643,5.505 v1(0.643,6.246)
  Bottom Layer w0.305: R54.1@-7.713,9.302 v1(-7.713,10.179) ; v1(7.548,4.911) 7.675,4.784 R21.2@8.429,4.784 ; v1(7.566,3.789) R22.2@8.429,3.789 ; R19.2@9.295,1.457 R19.2@9.295,1.457 R23.2@9.293,2.618 v1(10.243,2.618) ; v1(10.576,7.656) 11.651,7.656 C41.2@11.774,7.533 ; v1(13.861,-1.316) C37.2@13.861,-0.422 ; v2(17.373,2.315) 18.316,2.315 C53.1@18.476,2.155 ; C53.1@18.476,2.155 C54.2@19.638,2.155 ; C23.1@18.476,5.814 C52.2@19.635,5.814 20.119,5.814 20.357,5.576 v1(20.357,5.252) ; C31.2@19.641,-1.375 v1(20.36,-1.375) ; v1(22.137,-1.019) R32.2@22.137,-0.283
  Bottom Layer w0.381: C7.1@-8.758,15.452 v1(-8.758,16.517) ; R4.2@-0.175,11.489 v1(0.628,11.489) ; C49.1@-0.174,-22.31 0.643,-22.31 v1(1.044,-21.908) ; C46.1@-0.159,-16.955 v1(1.118,-16.955) ; v1(2.14,12.004) R2.2@2.14,12.707 ; R40.2@3.502,15.984 4.677,15.984 R9.2@4.68,15.981 5.443,15.981 v1(5.466,15.958) ; C28.1@3.611,0.652 3.659,0.7 v1(4.433,0.7) ; v1(10.776,-2.365) 10.787,-2.375 C56.2@10.787,-3.241 ; v1@13.102,-5.282 C33.2@13.102,-4.33 ; v1@15.401,-5.269 C34.2@15.401,-4.317 15.452,-4.368 C30.1@16.592,-4.368 ; C26.1@17.781,-4.368 C29.1@18.958,-4.368 v1(19.714,-4.368) ; C43.1@23.181,-3.294 v1(23.181,-2.423) ; C44.2@24.427,-7.406 24.331,-7.309 R33.2@24.331,-6.211 v1(25.07,-6.211)
  other v1: -13.217,-11.343 -13.217,-10.64 -13.217,-9.938 13.113,-5.292 15.412,-5.28 -24.074,-3.72 -23.372,-3.72 -22.67,-3.72 -13.217,-3.72 -24.074,-3.017 -23.372,-3.017 -22.67,-3.017 -13.217,-3.017 -24.074,-2.315 -23.372,-2.315 -22.67,-2.315 -13.217,-2.315 -5.947,-0.686 -5.058,-0.686 -4.169,-0.686 12.442,-0.528 -5.947,0.076 -5.058,0.076 -4.169,0.076 -5.947,0.838 -5.058,0.838 -4.169,0.838 -24.074,3.997 -23.372,3.997 -22.67,3.997 -13.217,3.997 -24.074,4.7 -23.372,4.7 -22.67,4.7 -24.074,5.402 -23.372,5.402 -22.67,5.402 -13.217,5.402 18.088,7.085 14.179,7.111 20.539,7.12 20.539,9.147 14.179,11.164 16.777,11.164 20.539,11.164 -18.701,11.786 -17.999,11.786 -17.296,11.786 16.345,12.156 17.187,12.156 18.029,12.156 18.871,12.156 -6.89,12.431 -6.103,12.431 -5.315,12.431 -18.701,12.488 -17.999,12.488 -17.296,12.488 16.345,12.884 17.187,12.884 18.029,12.884 18.871,12.884 -18.701,13.191 -17.999,13.191 -17.296,13.191 -6.89,13.447 -6.103,13.447 -5.315,13.447 -18.701,13.893 -17.999,13.893 -17.296,13.893 -6.89,14.463 -6.103,14.463 6.529,20.451 6.529,21.103 11.265,21.142 6.529,21.729 11.265,21.87 9.835,22.597 10.55,22.597 11.265,22.597 9.835,23.325 10.55,23.325 11.265,23.325
  other v2: 14.573,1.915 16.173,1.915 14.173,3.115 16.973,3.915 14.173,4.715
HIN1: C90.2 R115.2 U16.22 | length 4.5
  Top Layer w0.203: U16.22@-4.76,-1.841 -4.76,-2.556 -4.179,-3.137 -3.909,-3.137 -3.768,-3.278 C90.2@-3.768,-3.734 -3.768,-4.237 -3.85,-4.319 -4.461,-4.319 -4.708,-4.567 R115.2@-4.708,-5.005
HIN2: C112.2 R119.2 U16.23 | length 4.8
  Top Layer w0.203: U16.23@-4.26,-1.841 -4.26,-2.488 -3.981,-2.766 -2.639,-2.766 -2.334,-3.071 C112.2@-2.334,-3.862 -2.334,-4.885 R119.2@-2.215,-5.005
